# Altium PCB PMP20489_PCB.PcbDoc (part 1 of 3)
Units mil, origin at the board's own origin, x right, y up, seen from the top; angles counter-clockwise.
Board outline 4000 x 6000 mil, 8 copper layers (Top Layer, Signal Layer 1, Signal Layer 2, Signal Layer 3, Signal Layer 4, Signal Layer 5, Signal Layer 6, Bottom Layer), stack 63 mil thick; 331 components, 128 nets, 876 pads, 1027 vias.
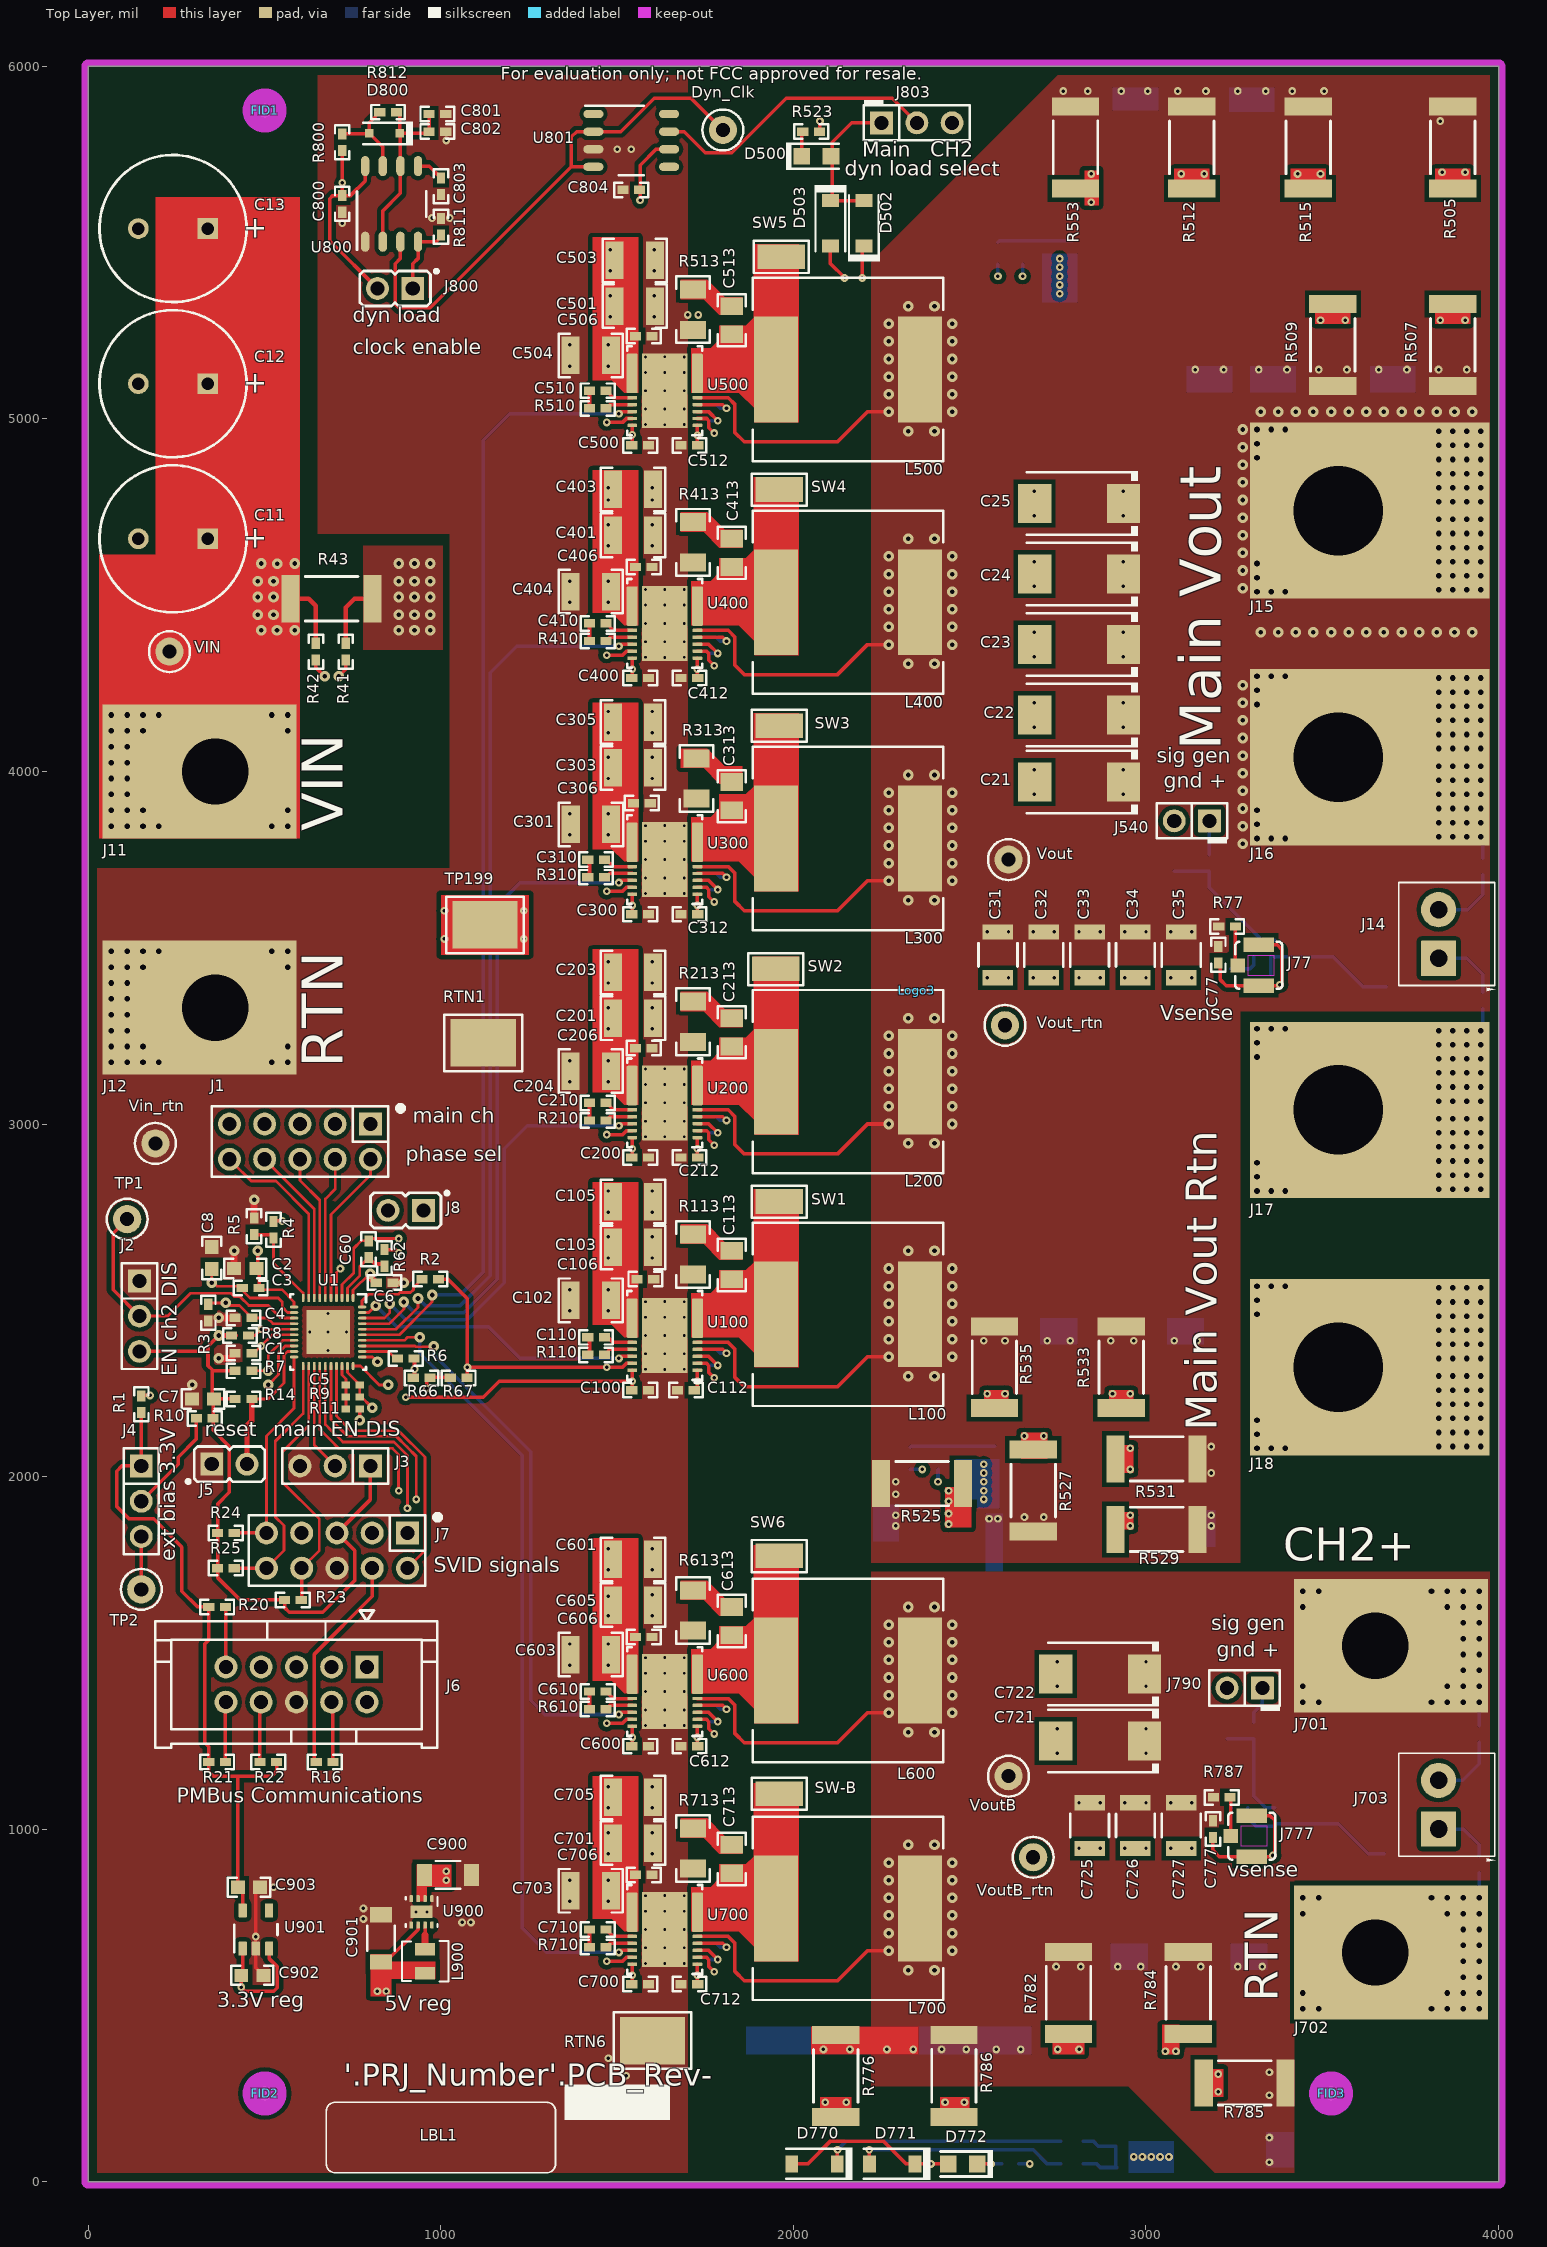
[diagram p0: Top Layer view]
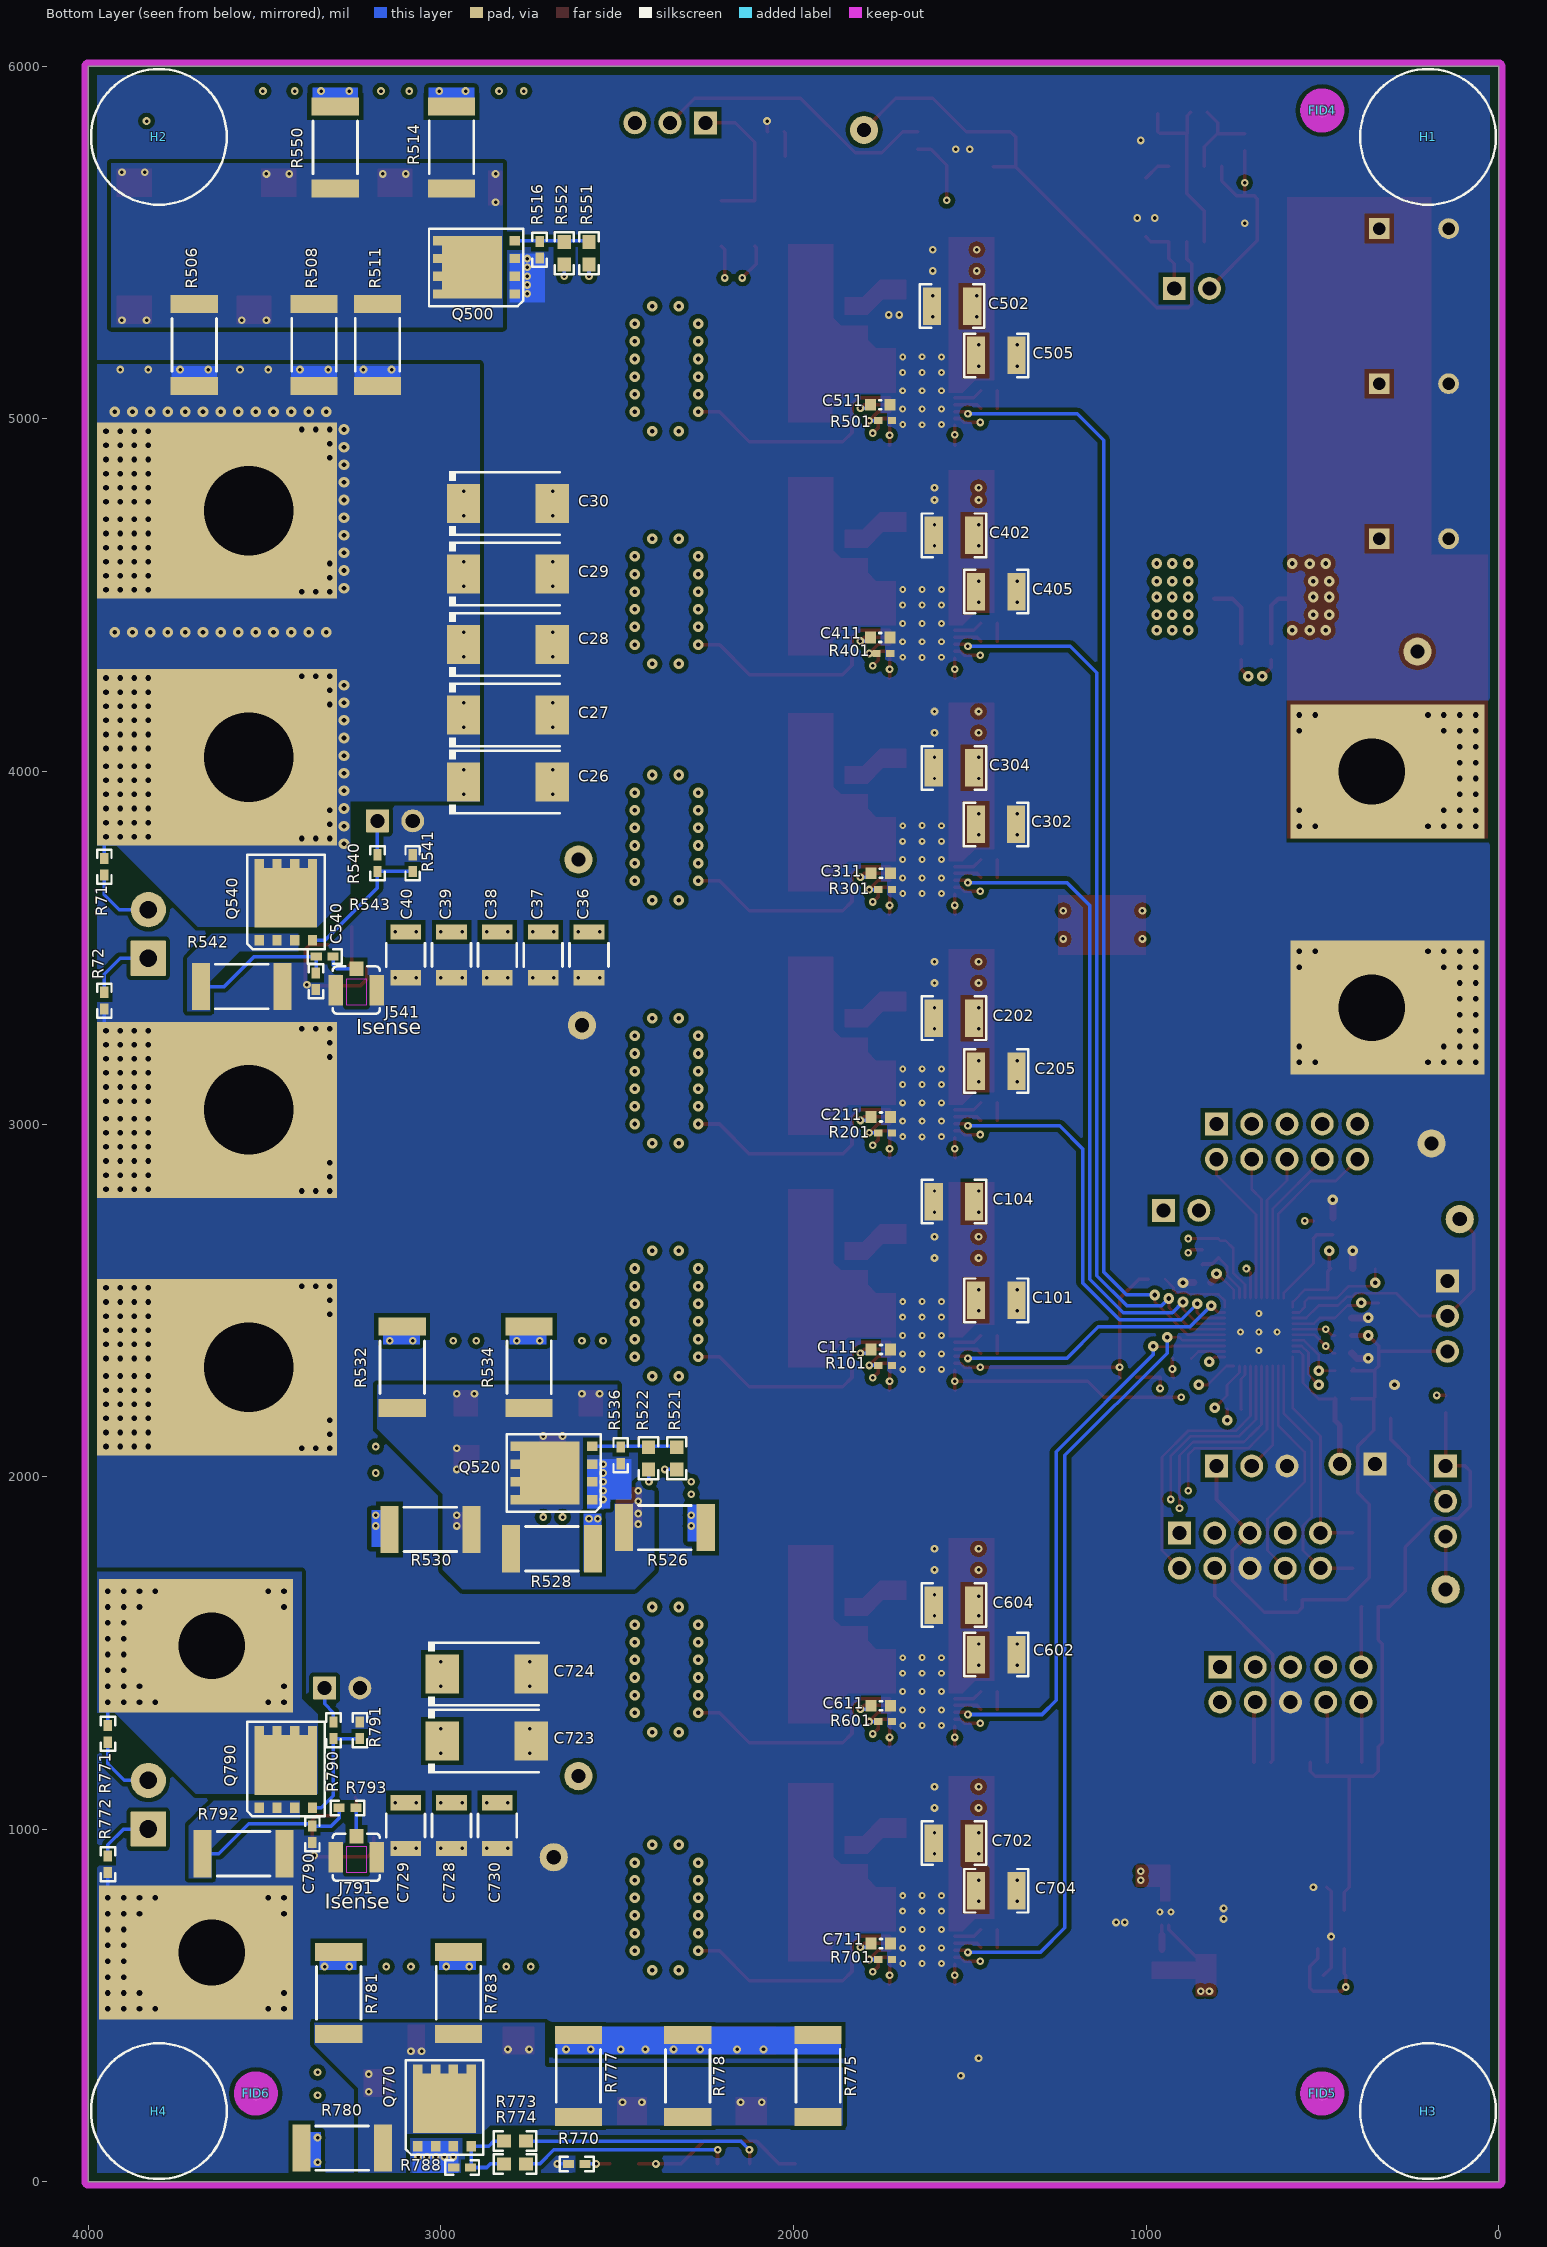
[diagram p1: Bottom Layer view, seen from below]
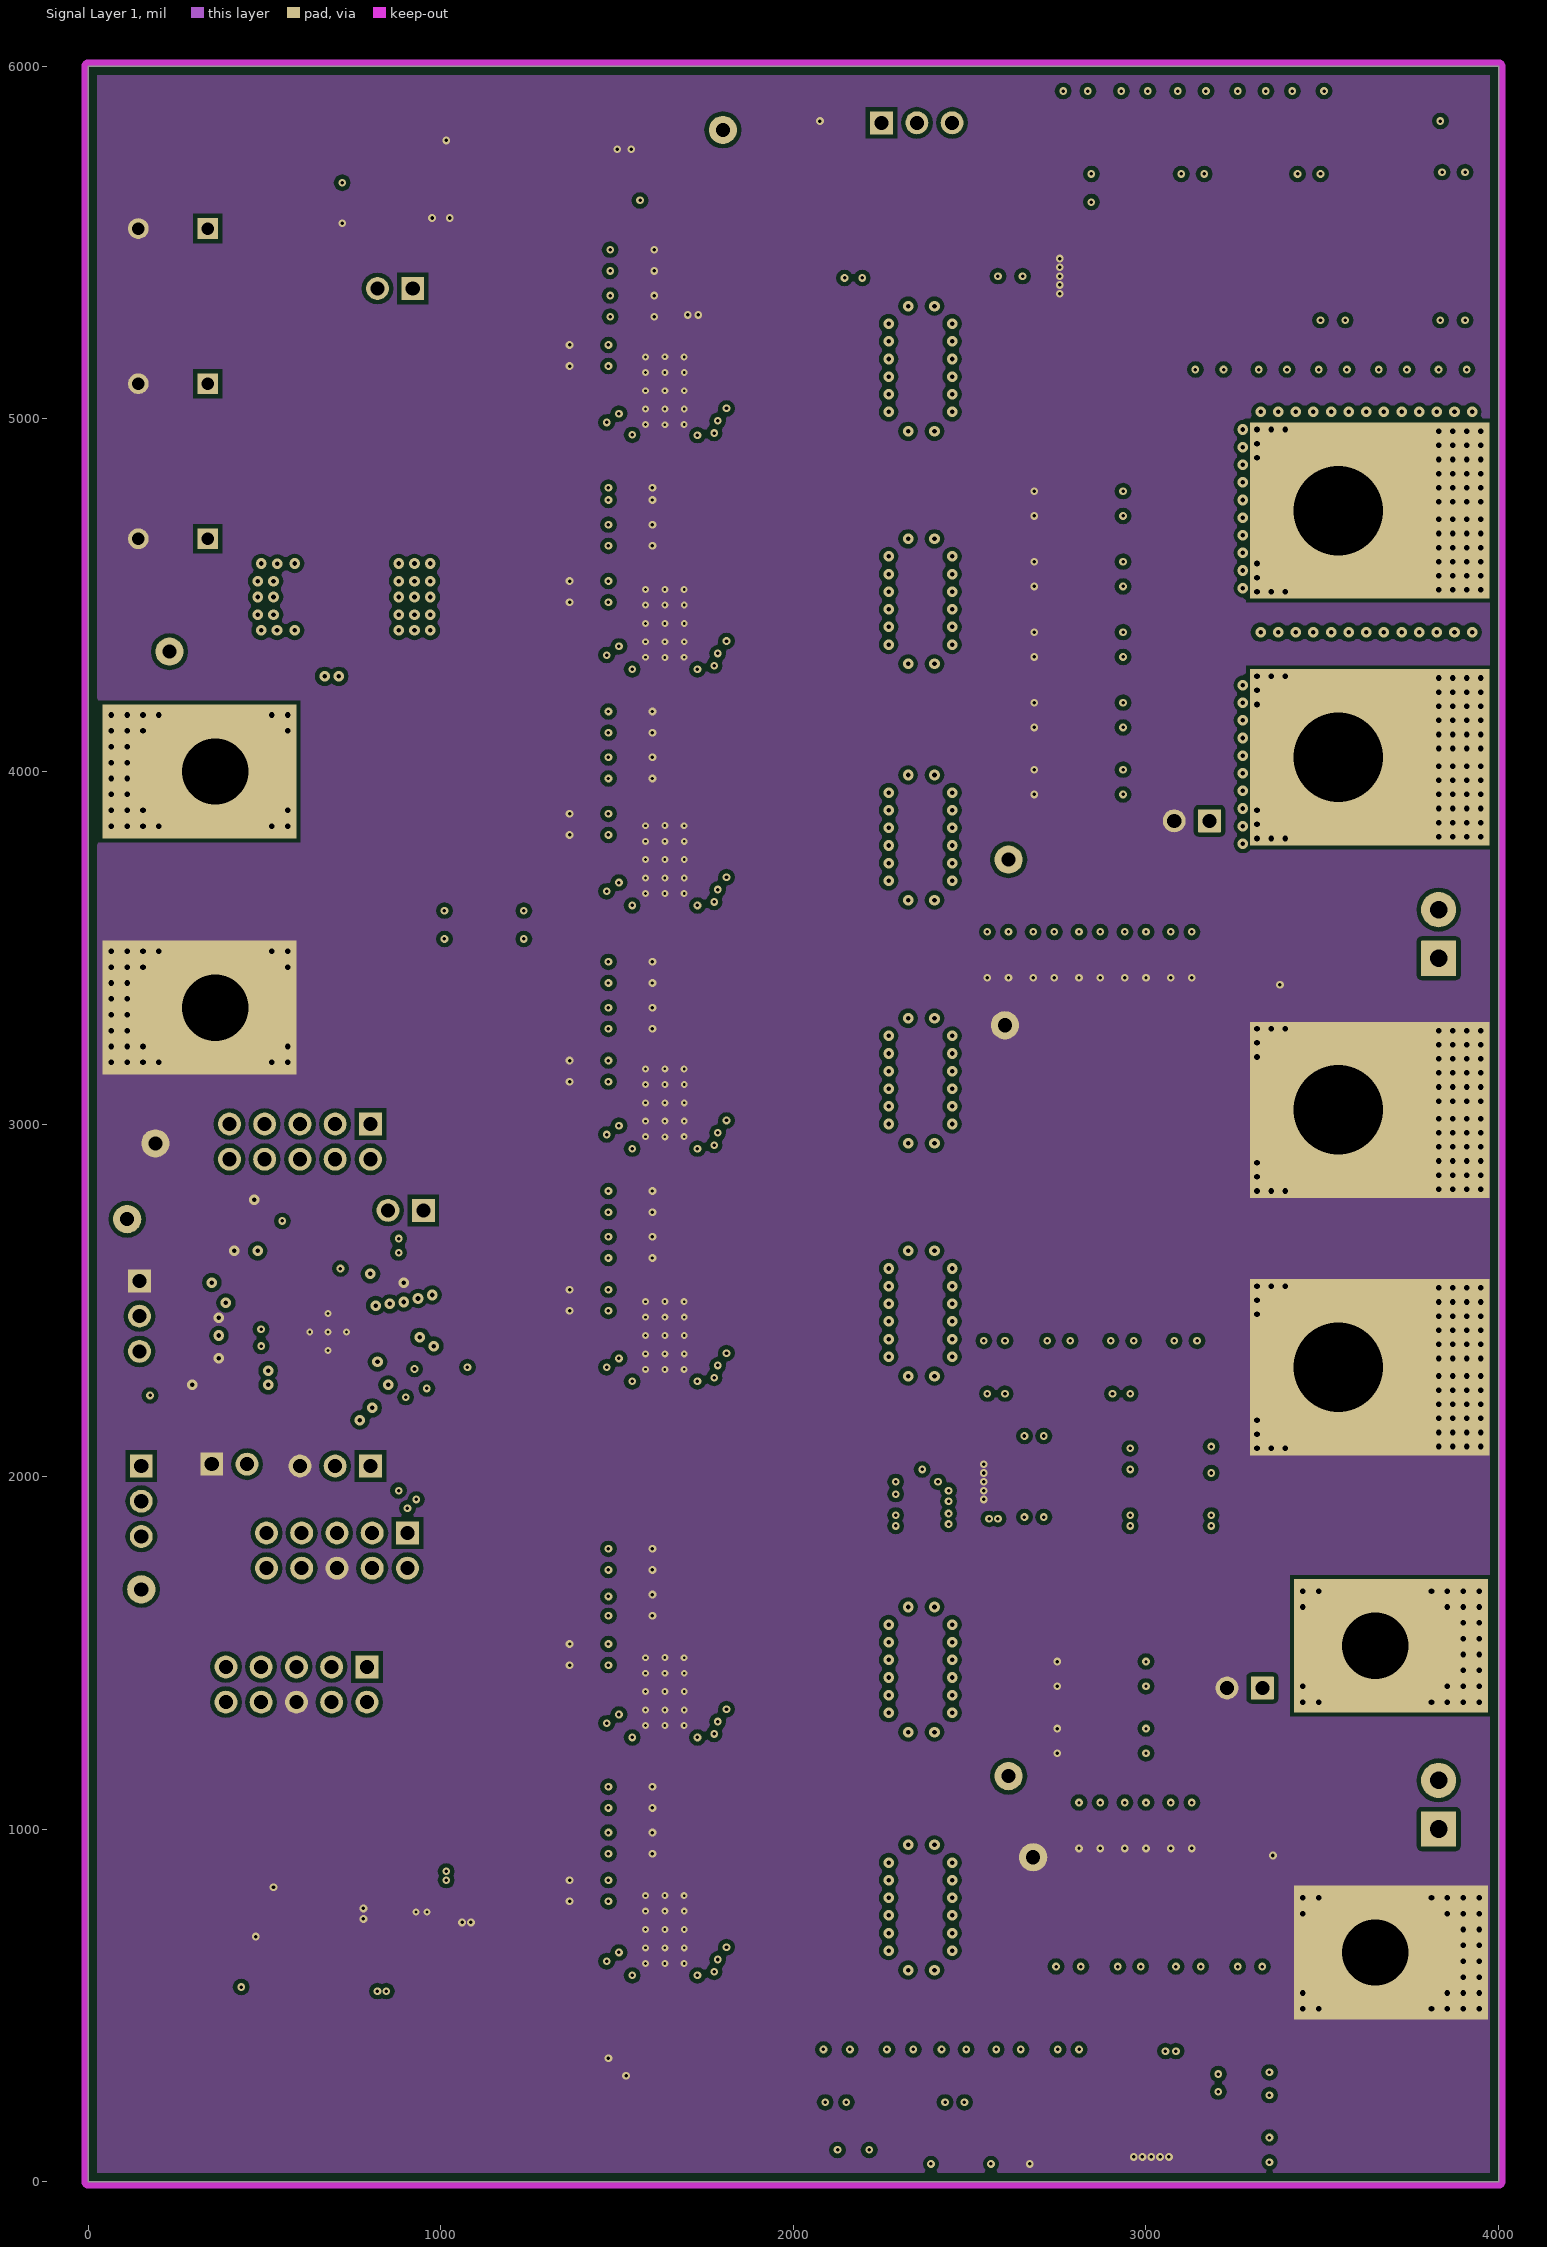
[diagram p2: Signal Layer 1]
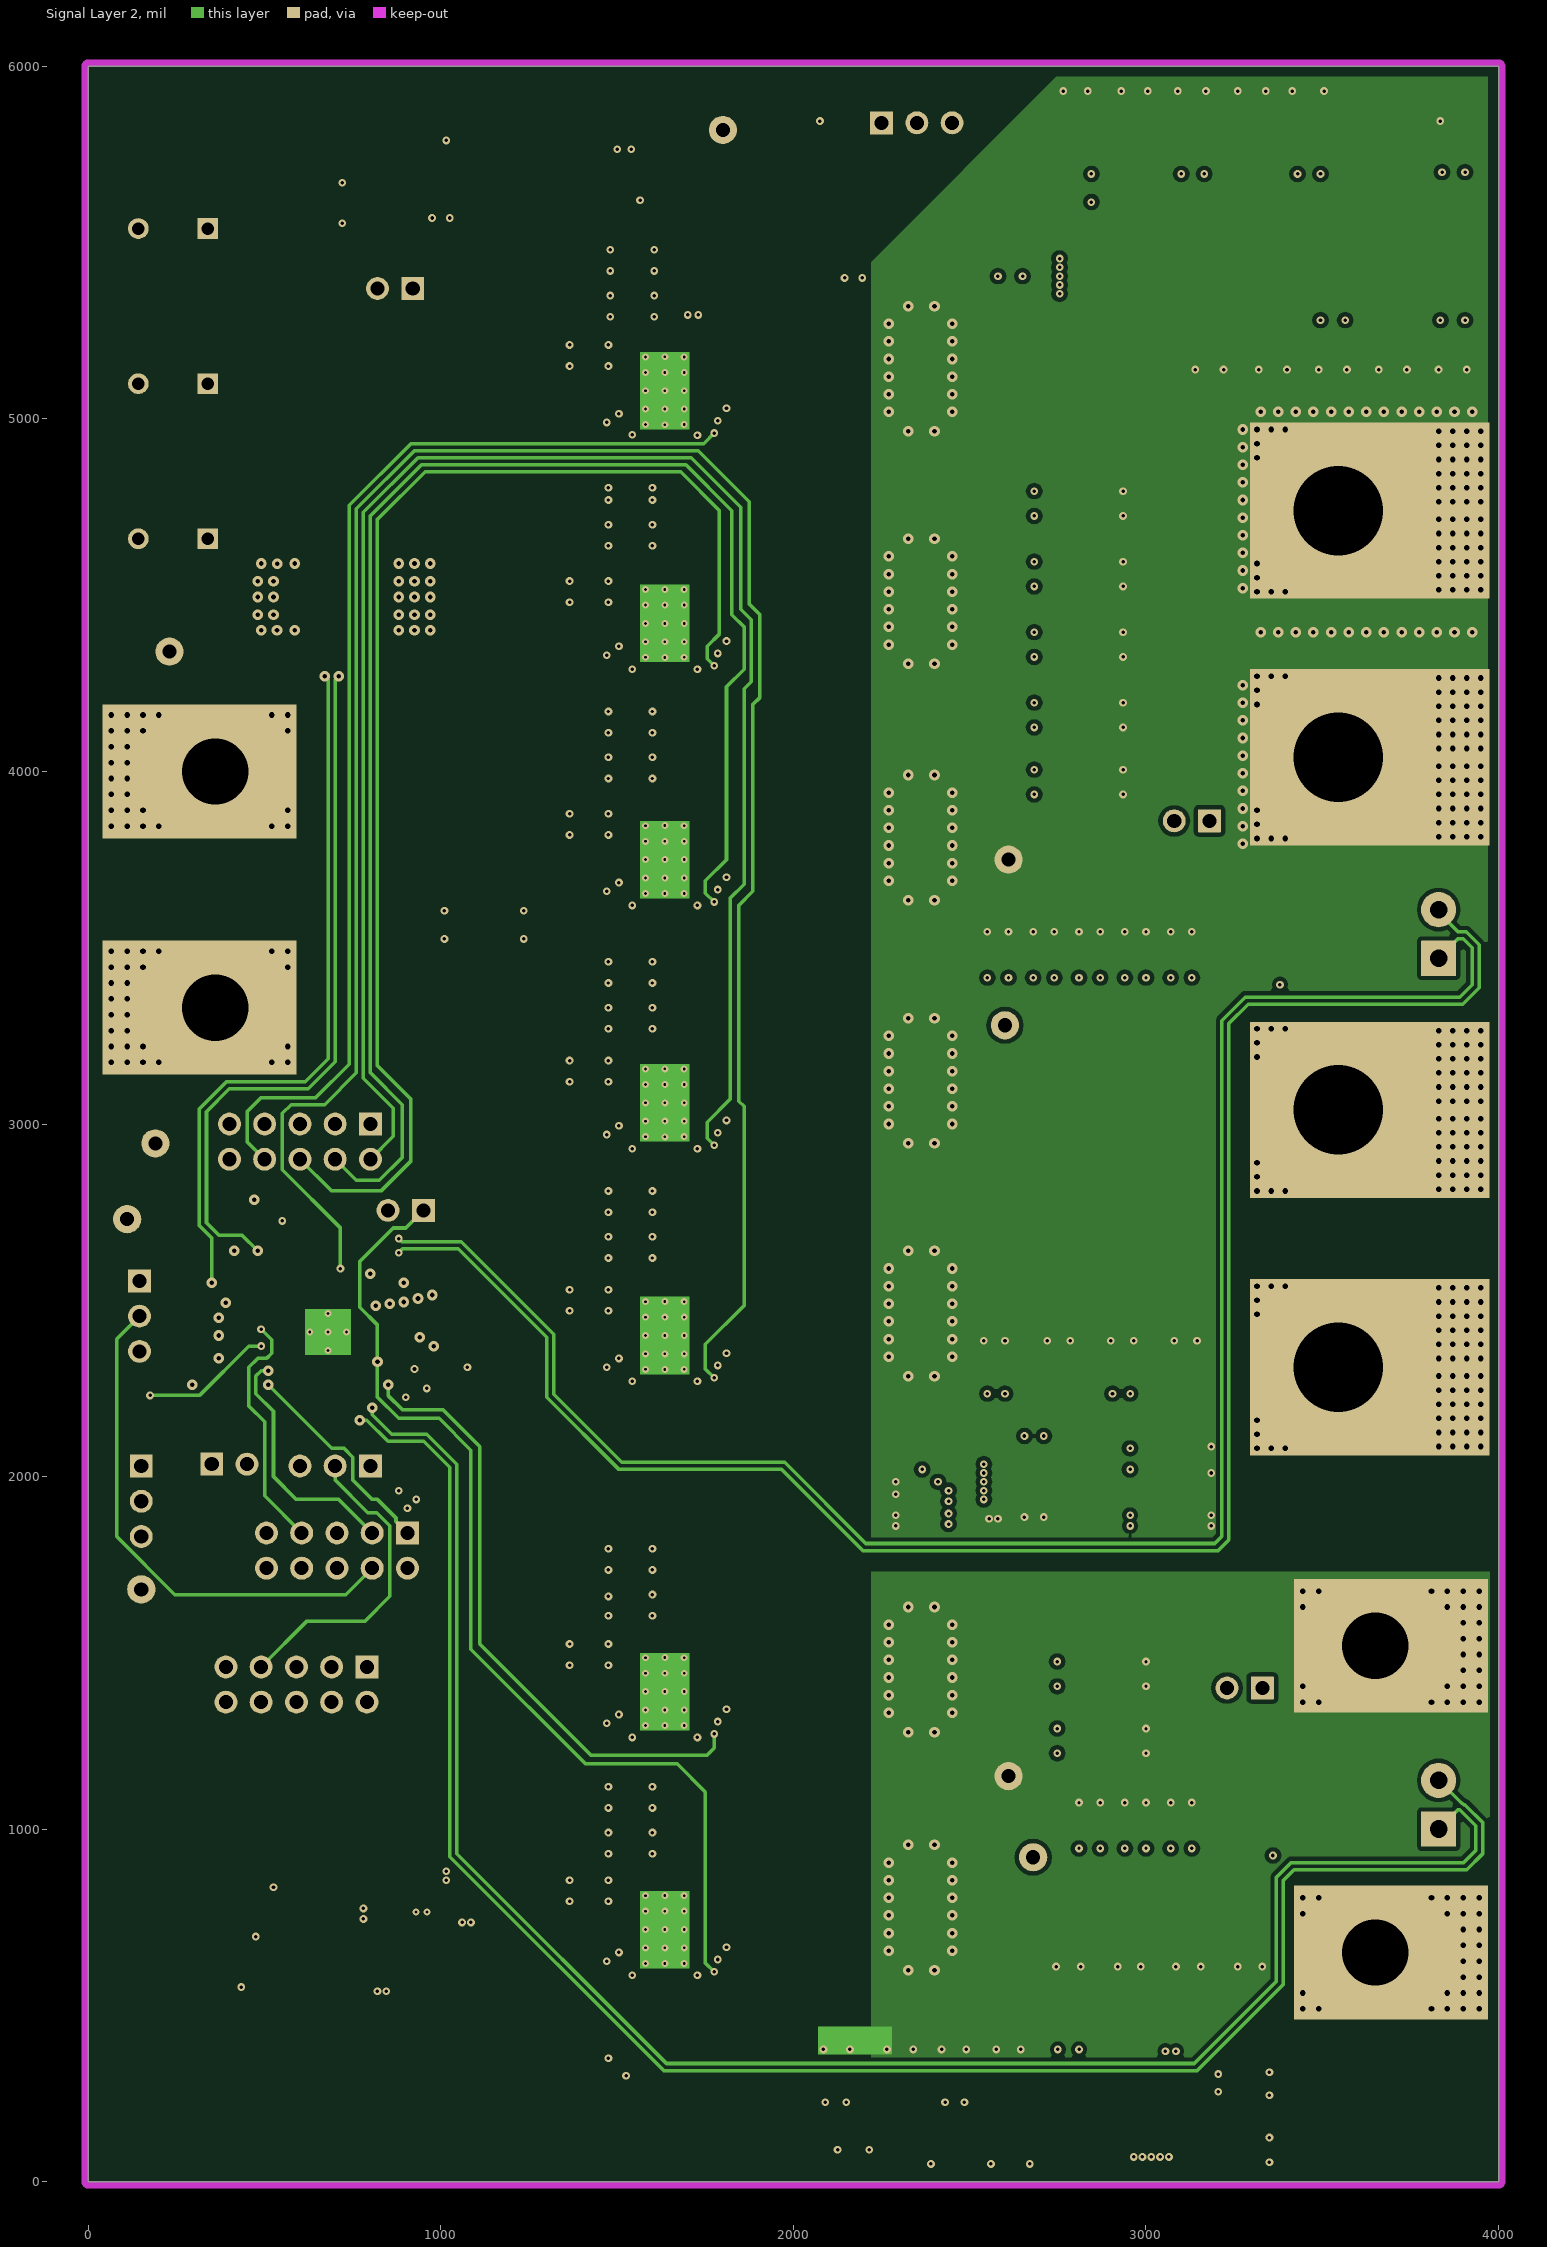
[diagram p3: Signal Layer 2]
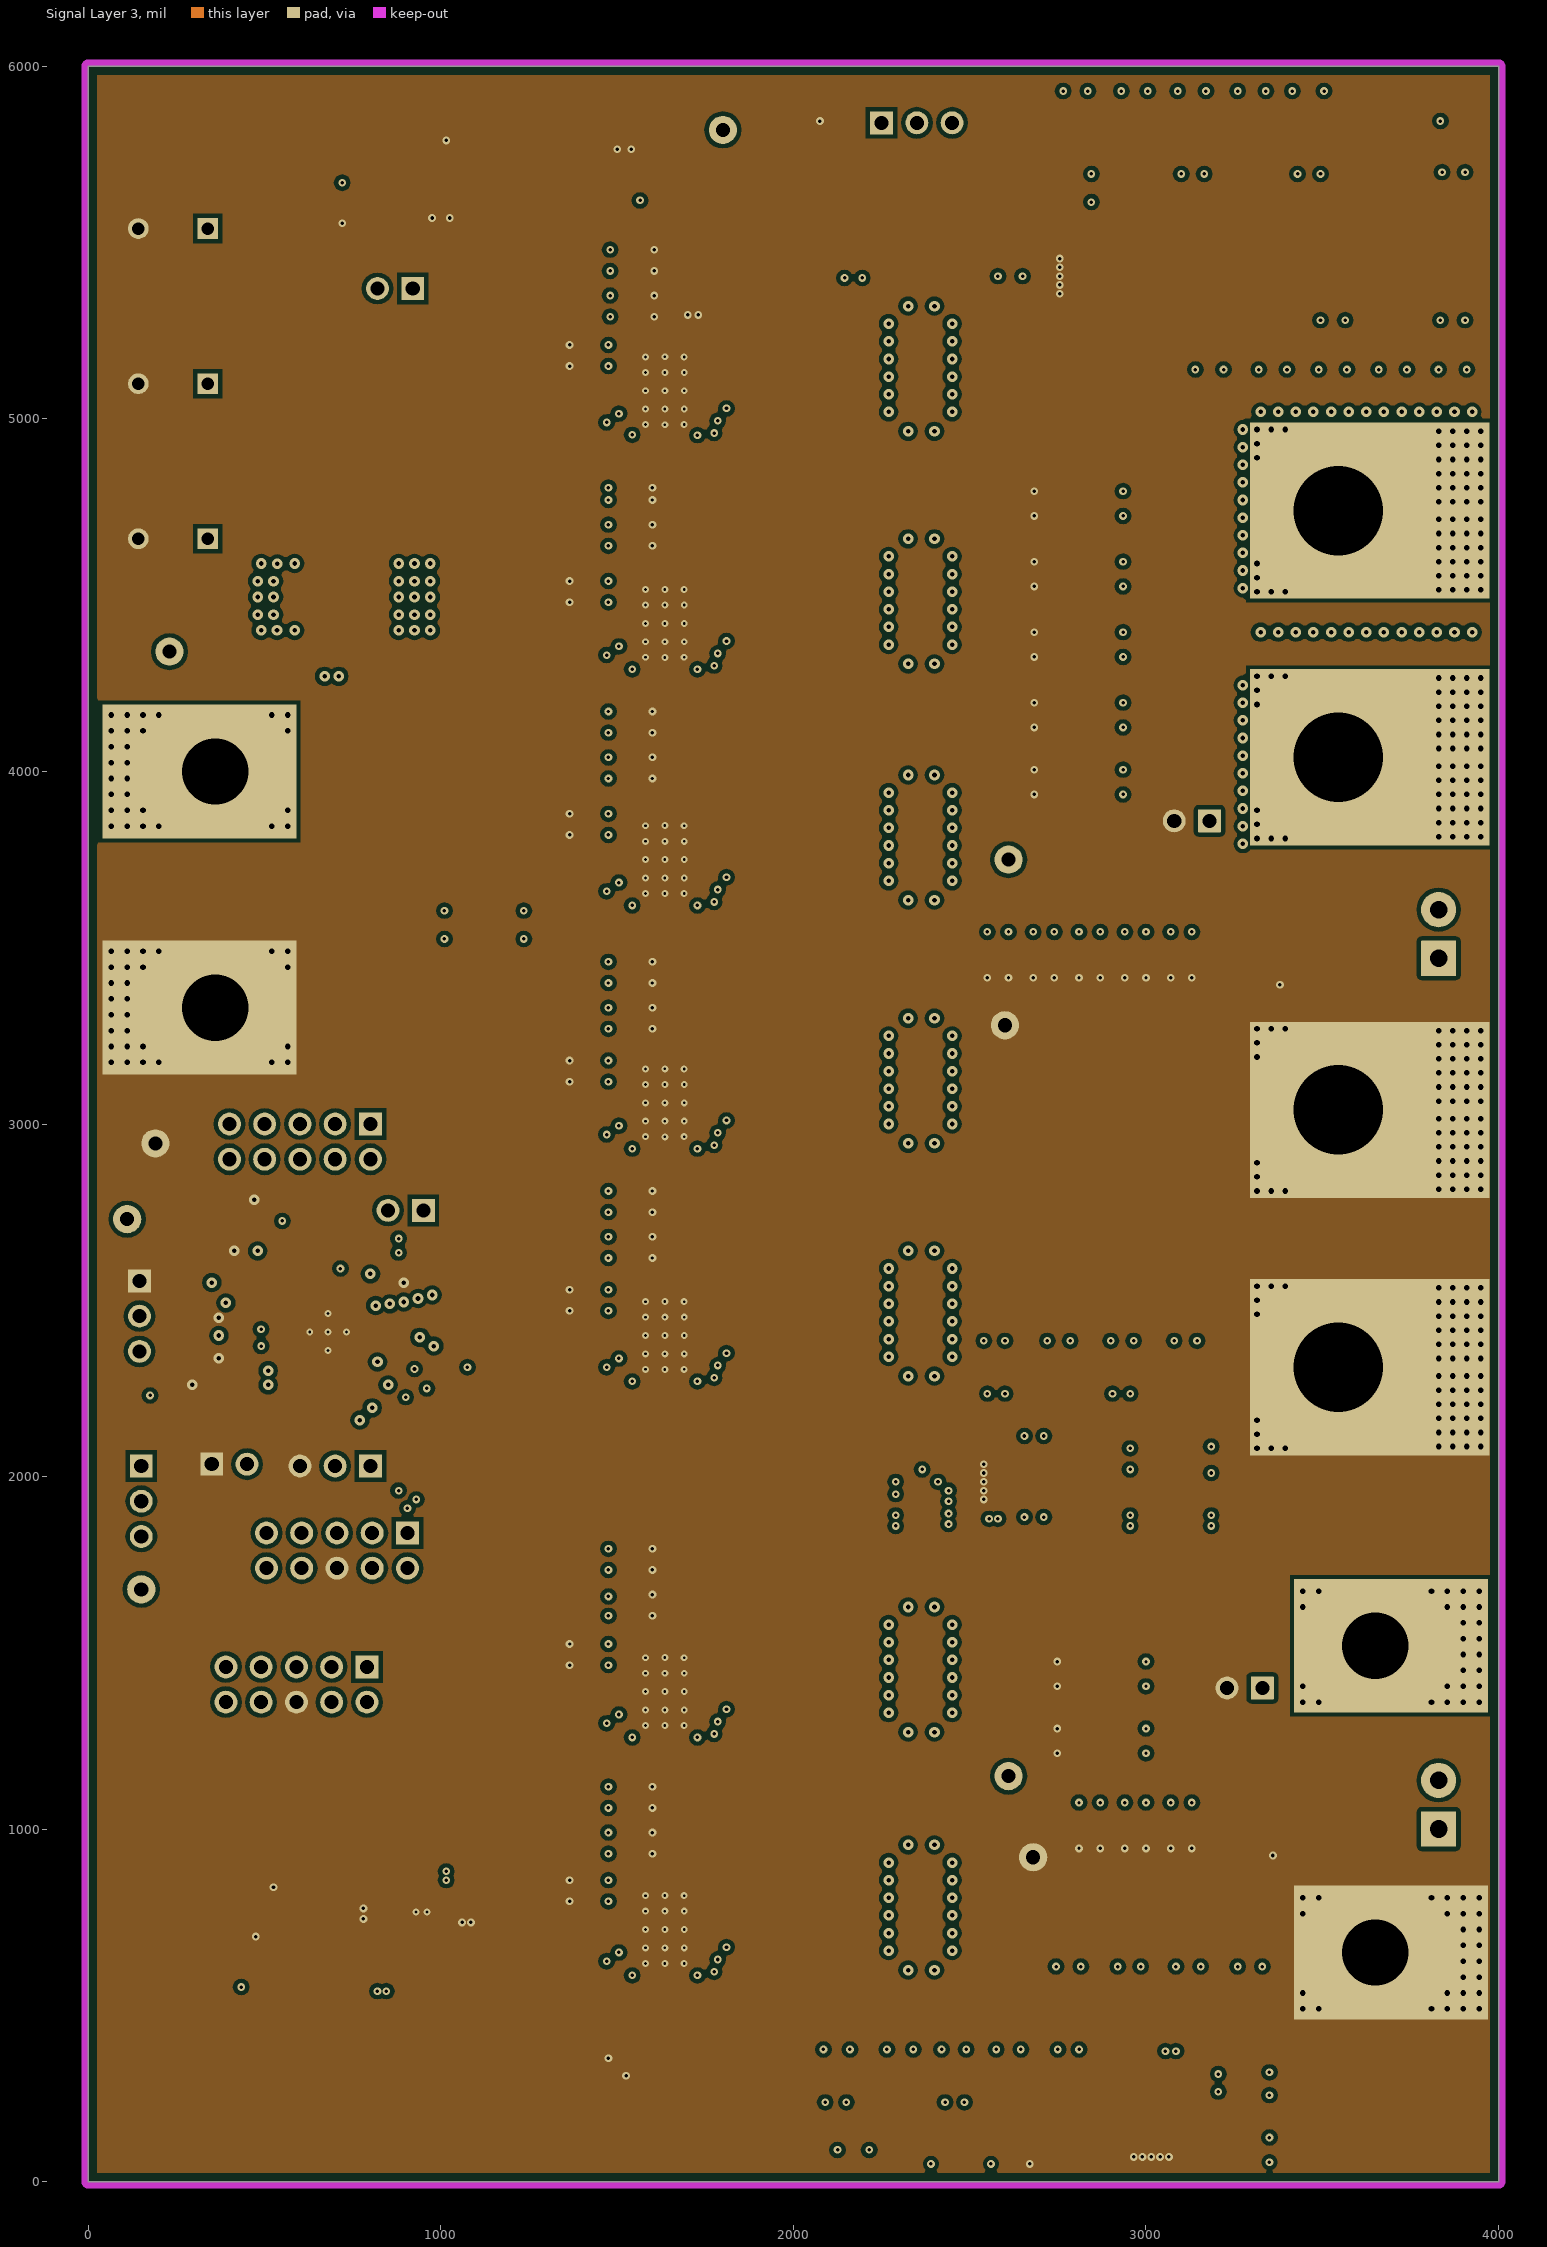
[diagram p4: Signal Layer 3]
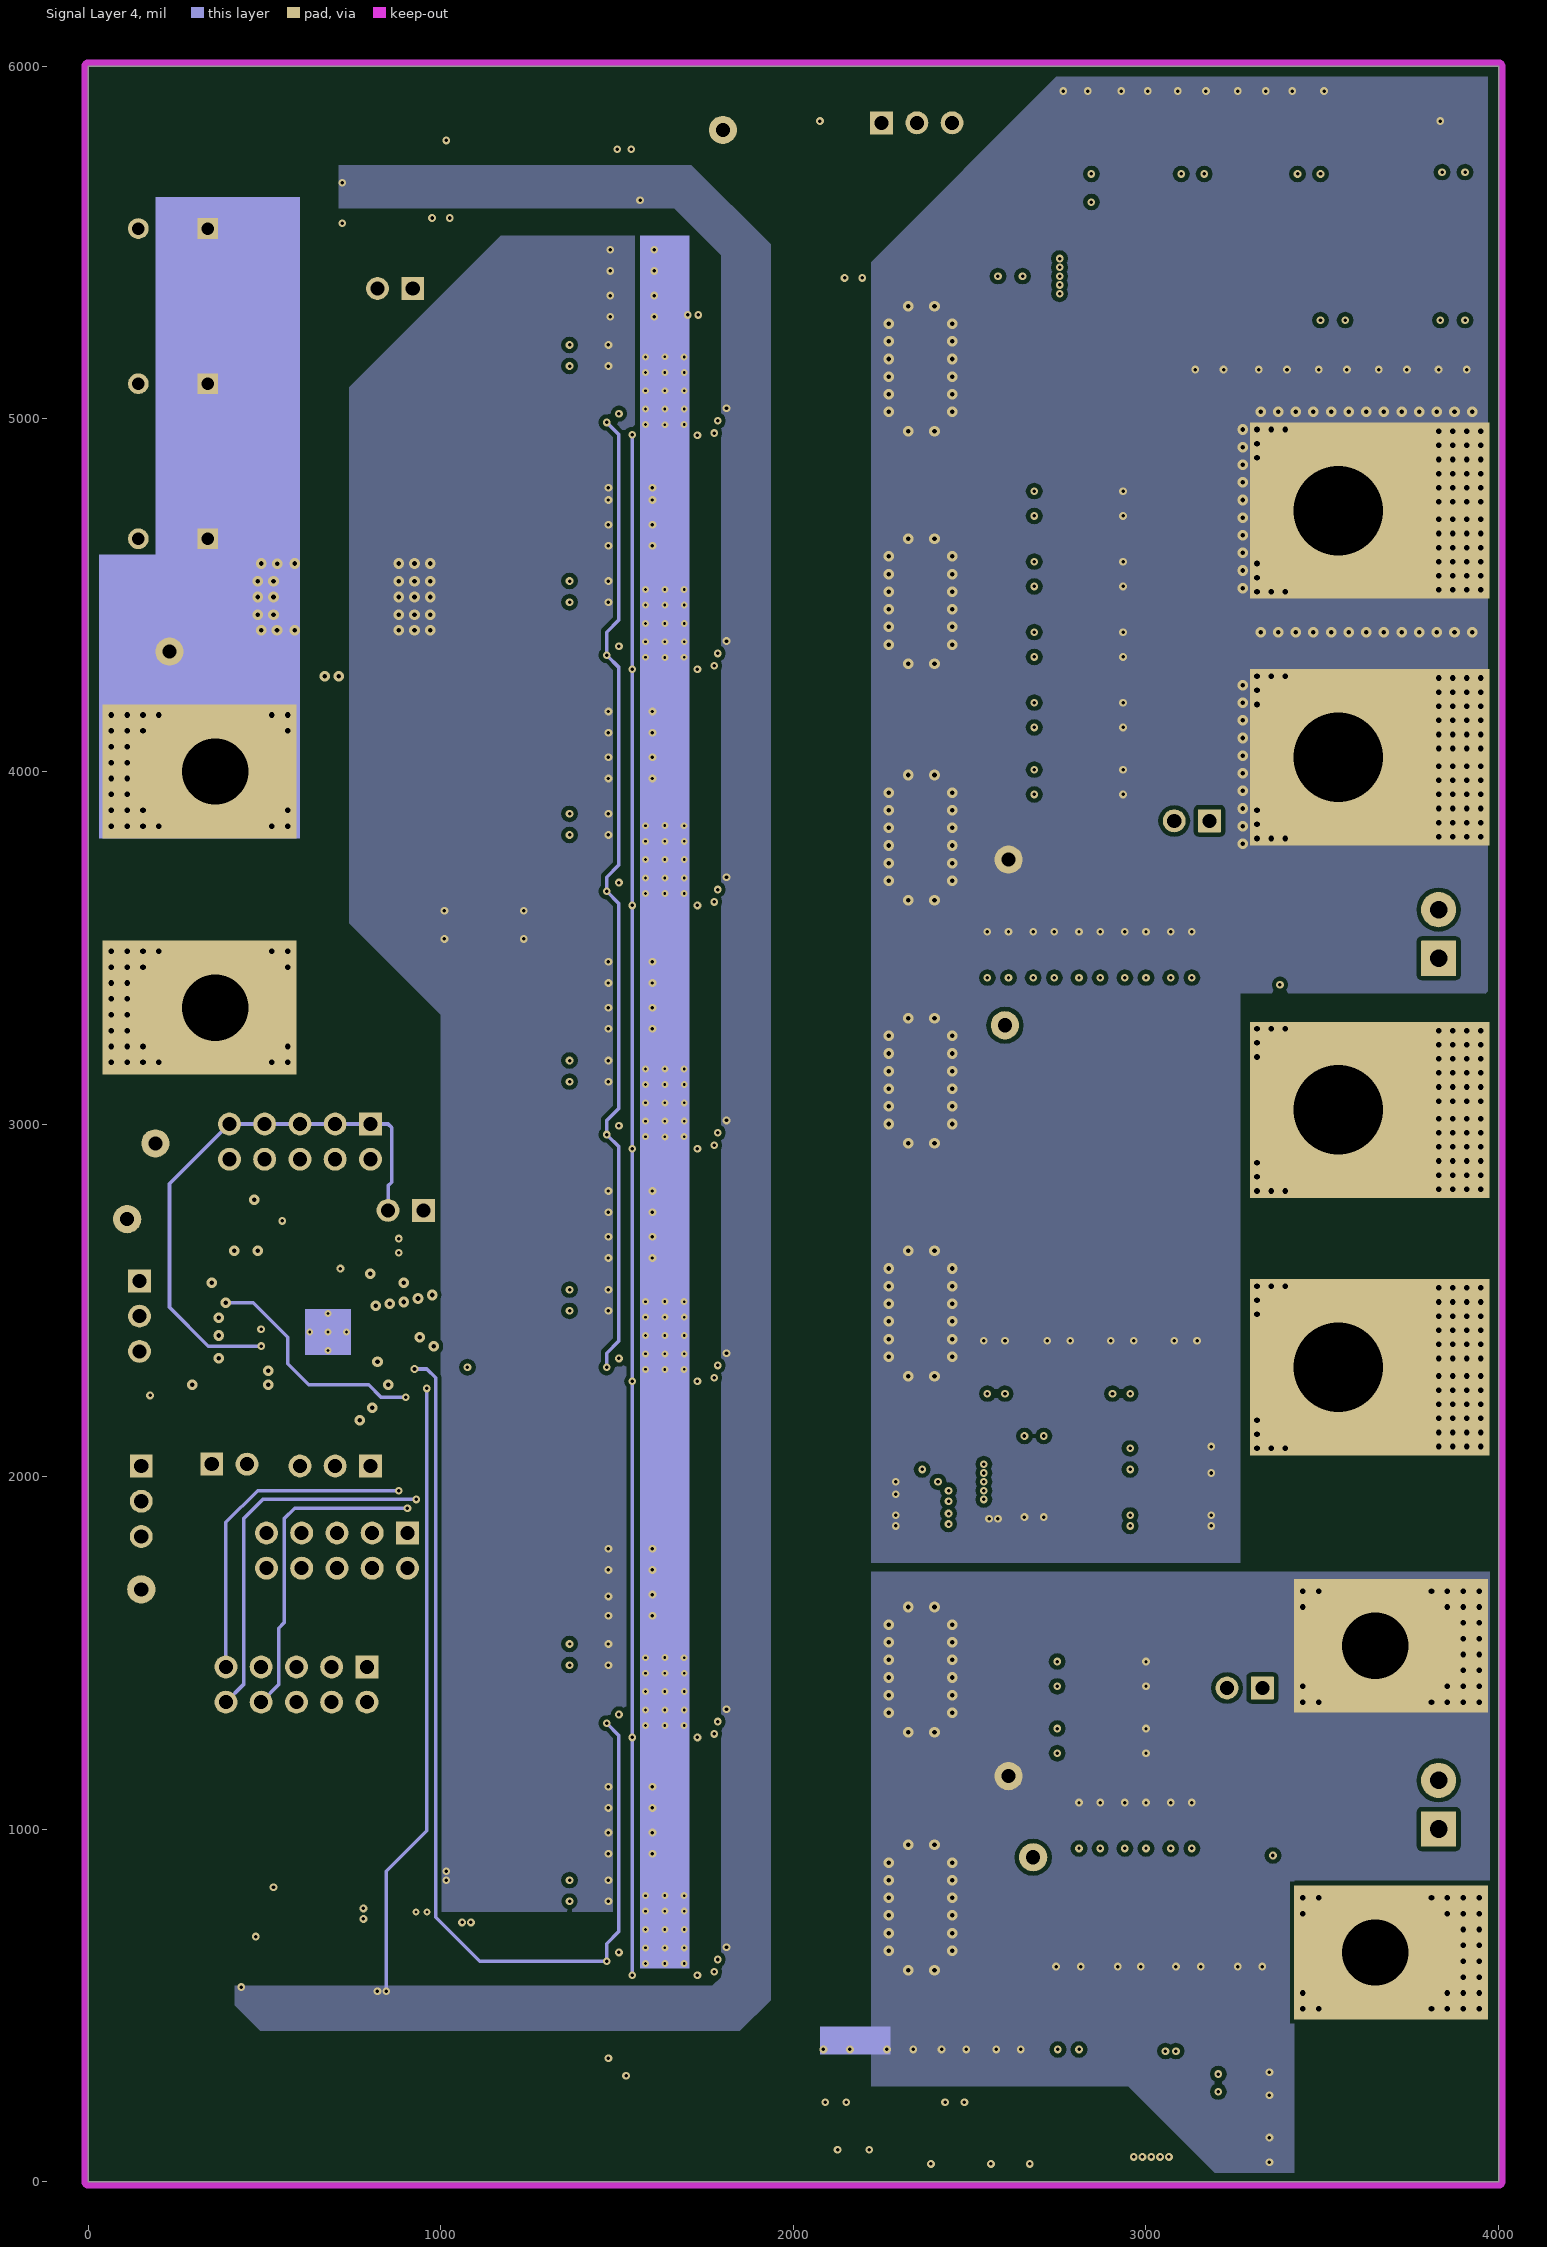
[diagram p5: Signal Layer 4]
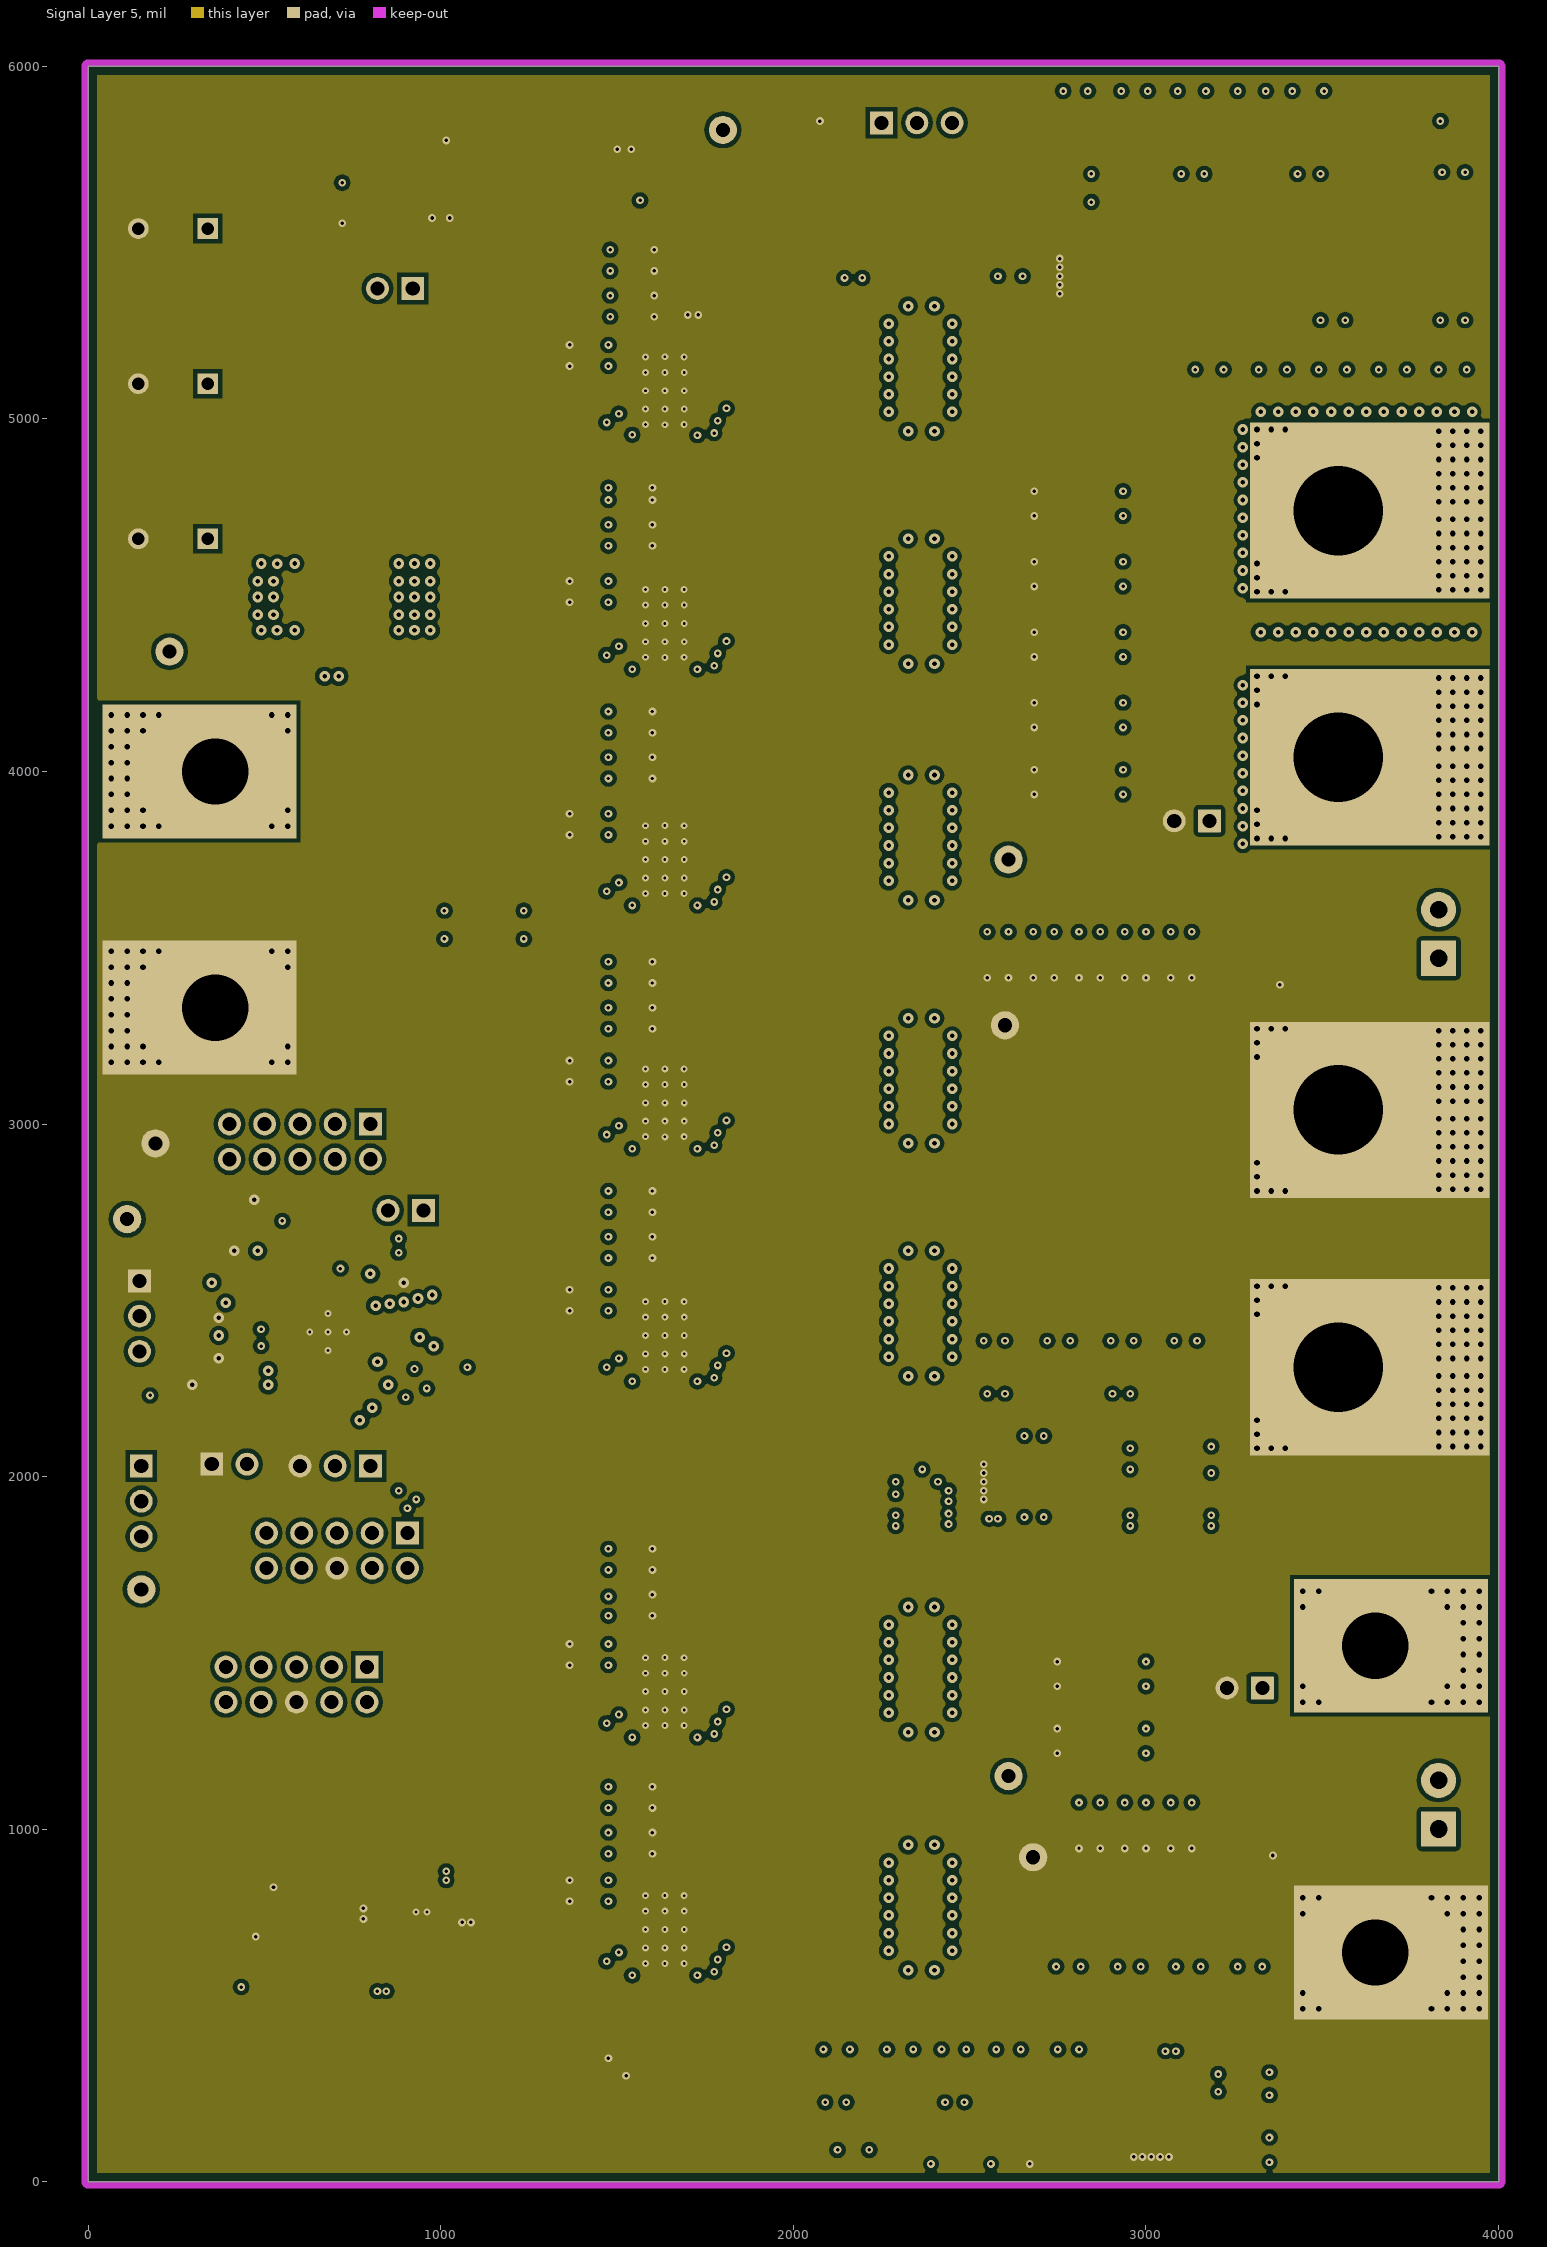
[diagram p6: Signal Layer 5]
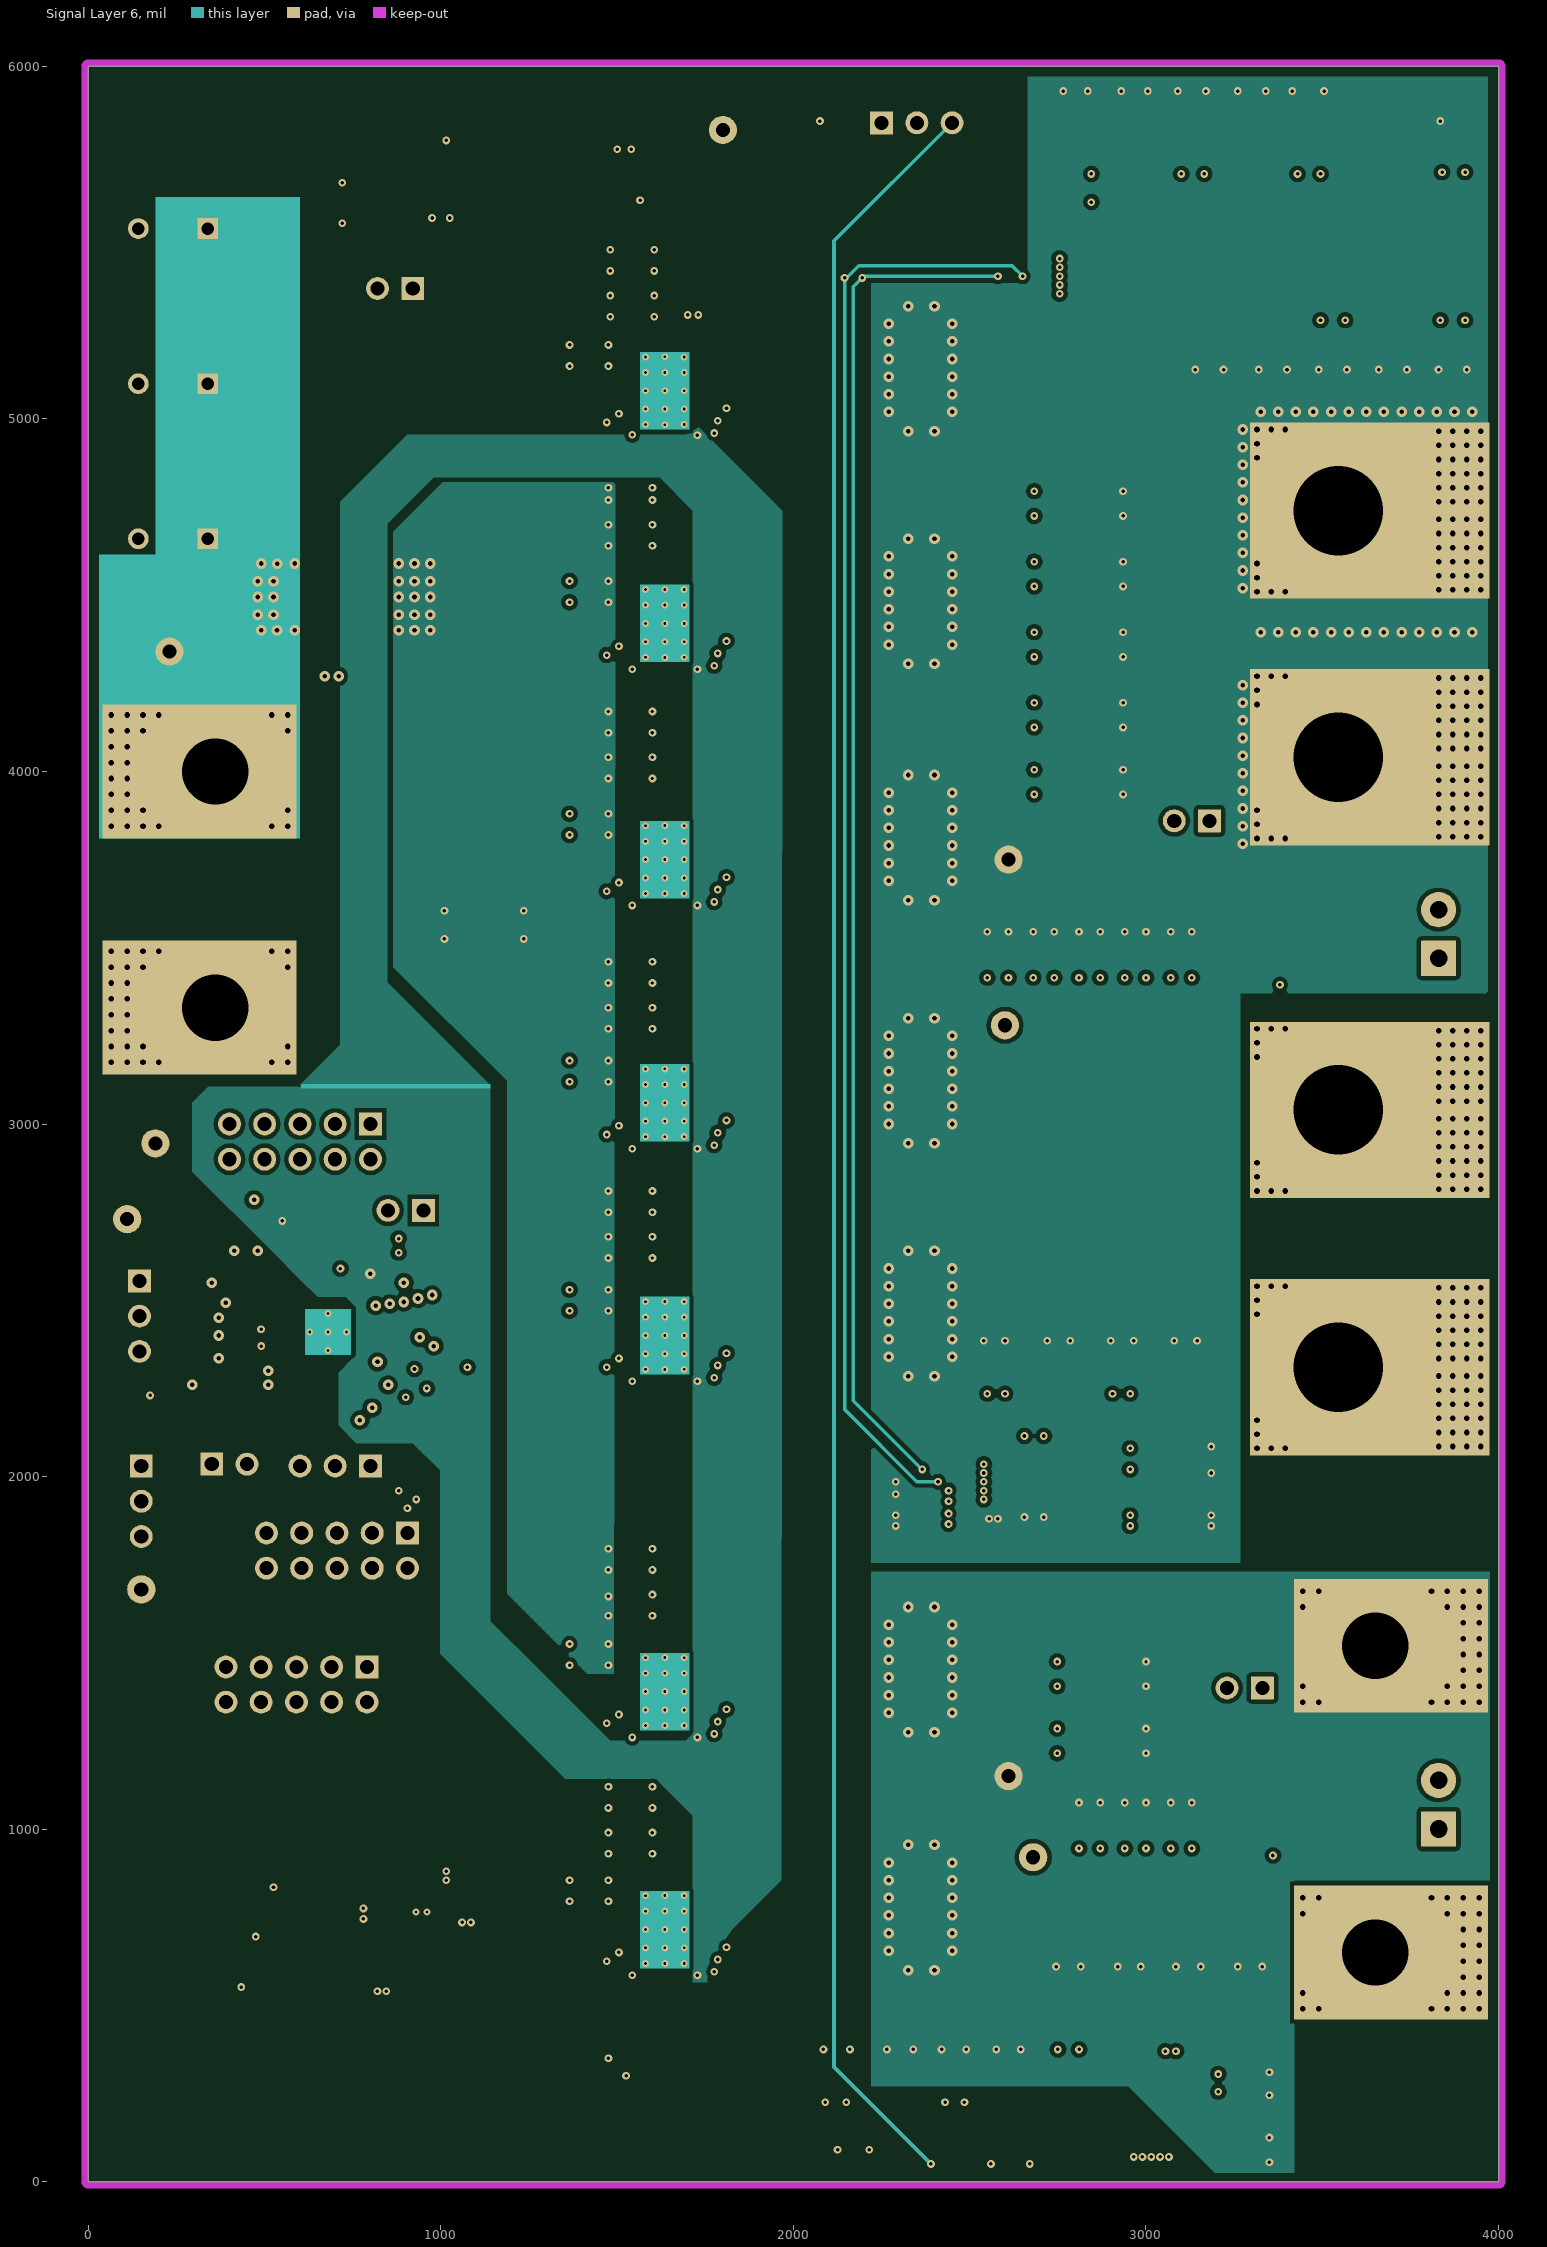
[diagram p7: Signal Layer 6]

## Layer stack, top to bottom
Top Solder: solder mask 0.4, Solder Resist, Dk 3.5
Top Layer: signal copper 2.1
Dielectric1: core 6, FR-4 High TG, Dk 4.8
Signal Layer 1: signal copper 2.8
Dielectric 3: prepreg 6, FR-4 High TG, Dk 4.8
Signal Layer 2: signal copper 2.8
Dielectric 4: core 6, FR-4 High TG, Dk 4.8
Signal Layer 3: signal copper 2.8
Dielectric 5: prepreg 6, FR-4 High TG, Dk 4.8
Signal Layer 4: signal copper 2.8
Dielectric 6: core 6, FR-4 High TG, Dk 4.8
Signal Layer 5: signal copper 2.8
Dielectric 7: prepreg 6, FR-4 High TG, Dk 4.8
Signal Layer 6: signal copper 2.8
Dielectric 2: core 6, FR-4 High TG, Dk 4.8
Bottom Layer: signal copper 2.1
Bottom Solder: solder mask 0.4, Solder Resist, Dk 3.5

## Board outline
0,0 4000,0 4000,6000 0,6000

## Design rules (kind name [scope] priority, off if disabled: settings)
AcuteAngle [All] p1: minimum=4.50000000000000E+0001 checktracksonly=FALSE
AssemblyTestPointUsage [All] p1: valid=2
BoardOutlineClearance BoardOutlineClearance_MountingHoles [OnCopper and InComponentClass('Mounting Holes')] p1: gap=40
BoardOutlineClearance BoardOutlineClearance_Poly [OnCopper and IsPoly] p2: gap=25
BoardOutlineClearance [OnCopper and Not InComponentClass('Logo') and not InComponentClass('FiducialMark') and not InRegion(1000,500,4000,800) and not InPoly] p3: gap=25
Clearance Clearance_Keepouts [((IsTrack Or IsArc) And Not InPoly) And IsFree and IsKeepOut vs ((IsTrack Or IsArc) And Not InPoly) And IsFree and IsKeepOut] p1: gap=0
Clearance Clearance_Poly [InPolygon] p2: gap=12
Clearance [All] p3: gap=7.8
ComponentClearance ComponentClearance_MountingHoles_FiducialMarks [InComponentClass('Mounting Holes') vs InComponentClass('FiducialMark')] p1: gap=50 collisioncheckmode=3 verticalgap=10 showdistances=FALSE
ComponentClearance ComponentClearance_Shunt [InComponentClass('Header') vs InComponentClass('Shunt')] p2: gap=0 collisioncheckmode=3 verticalgap=0 showdistances=FALSE
ComponentClearance ComponentClearance_Logo [InComponentClass('Logo')] p3: gap=50 collisioncheckmode=3 verticalgap=10 showdistances=FALSE
ComponentClearance ComponentClearance_ScrewToNut [(HasFootprint('NY PMS 440 0025 PH')) vs (HasFootprint('Keystone_1902C'))] p4: gap=5 collisioncheckmode=3 verticalgap=10 showdistances=FALSE
ComponentClearance ComponentClearance_MountingHoles [InComponentClass('Mounting Holes')] p5: gap=150 collisioncheckmode=3 verticalgap=150 showdistances=FALSE
ComponentClearance ComponentClearance_SmallPassives [HasFootprint('0201*') or HasFootprint('0402*') or HasFootprint('0508') or HasFootprint('0603*') or HasFootprint('0612') or HasFootprint('0805*') or HasFootprint('0815*') or HasFootprint('0830*') or HasFootprint('1206*') or HasFootprint('1210*') or HasFootprint('1808*') or HasFootprint('1812*') or HasFootprint('1825*') or HasFootprint('2010*') or HasFootprint('2220*') or HasFootprint('2225*') or HasFootprint('2512*') or HasFootprint('2728*') or HasFootprint('3518*') vs HasFootprint('0201*') or HasFootprint('0402*') or HasFootprint('0508') or HasFootprint('0603*') or HasFootprint('0612') or HasFootprint('0805*') or HasFootprint('0815*') or HasFootprint('0830*') or HasFootprint('1206*') or HasFootprint('1210*') or HasFootprint('1808*') or HasFootprint('1812*') or HasFootprint('1825*') or HasFootprint('2010*') or HasFootprint('2220*') or HasFootprint('2225*') or HasFootprint('2512*') or HasFootprint('2728*') or HasFootprint('3518*')] p6: gap=10 collisioncheckmode=3 verticalgap=10 showdistances=FALSE
ComponentClearance ComponentClearance_THtoSMT [IsThruComponent vs IsSMTComponent] p7: gap=20 collisioncheckmode=3 verticalgap=20 showdistances=FALSE
ComponentClearance ComponentClearance_THtoTH [IsThruComponent vs IsThruComponent] p8: gap=20 collisioncheckmode=3 verticalgap=20 showdistances=FALSE
ComponentClearance [All] p9: gap=10 collisioncheckmode=3 verticalgap=10 showdistances=FALSE
DiffPairsRouting [All] p1: maxlimit=100 minlimit=10 mostfreqgap=10 toplayer_minwidth=15 toplayer_maxwidth=15 toplayer_prefwidth=15 midlayer1_minwidth=15 midlayer1_maxwidth=15 midlayer1_prefwidth=15 midlayer2_minwidth=15 midlayer2_maxwidth=15 midlayer2_prefwidth=15 midlayer3_minwidth=15 midlayer3_maxwidth=15 midlayer3_prefwidth=15 midlayer4_minwidth=15 midlayer4_maxwidth=15 midlayer4_prefwidth=15 midlayer5_minwidth=15 midlayer5_maxwidth=15 midlayer5_prefwidth=15 midlayer6_minwidth=15 midlayer6_maxwidth=15 midlayer6_prefwidth=15 bottomlayer_minwidth=15 bottomlayer_maxwidth=15 bottomlayer_prefwidth=15 maxuncoupledlength=1000
FabricationTestPointUsage TestPointUsage [All] p1: valid=2 allowmultiple=FALSE
FabricationTestpoint Testpoint [All] p1: side=3 testpointundercomponent=TRUE minsize=40 maxsize=100 preferedsize=60 minholesize=0 maxholesize=40 preferedholesize=32 testpointgrid=1 allowsidetop=TRUE allowsidebottom=TRUE usegrid=TRUE gridtolerance=0.01
FanoutControl Fanout_LCC [IsLCC] p1: bgadir=Out bgaviamode=Centered fanoutstyle=Auto fanoutdirection=Alternating viagrid=1 // Fanout_LCC (Default Rule)
FanoutControl Fanout_BGA [IsBGA] p2: bgadir=Out bgaviamode=Centered fanoutstyle=Auto fanoutdirection=Alternating viagrid=1 // Fanout_BGA (Default Rule)
FanoutControl Fanout_Default [All] p4: bgadir=Out bgaviamode=Centered fanoutstyle=Auto fanoutdirection=Alternating viagrid=1 // Fanout_Default (Default Rule)
FanoutControl Fanout_Small [(CompPinCount < 5)] p5: bgadir=Out bgaviamode=Centered fanoutstyle=Auto fanoutdirection=OutThenIn viagrid=1 // Fanout_Small (Default Rule)
HoleSize [All] p1: absolutevalues=TRUE maxlimit=255 minlimit=7.87 maxpercent=80.000 minpercent=20.000
MinimumAnnularRing MinimumAnnularRing_ThermalPadVias [IsVia and InAnyComponent] p1: minimumring=5.91
MinimumAnnularRing [All] p2: minimumring=5.9
MinimumSolderMaskSliver MinimumSolderMaskSliver_Logo [InComponentClass('Logo') vs InComponentClass('Logo')] p1: minsoldermaskwidth=0.7
MinimumSolderMaskSliver [All] p2: minsoldermaskwidth=3.94
PlaneConnect [All] p1: planeconnectstyle=Relief reliefexpansion=10 reliefentries=4 reliefconductorwidth=10 reliefairgap=10
PolygonConnect [All] p1: connectstyle=Direct reliefconductorwidth=10 reliefentries=4 polygonreliefangle="90 Angle" airgapwidth=10
RoutingVias ThermalPadVias [IsVia and InAnyComponent] p1: holewidth=7.87 width=19.68 viastyle="Through Hole" minholewidth=7.87 minwidth=19.68 maxholewidth=16 maxwidth=32
RoutingVias [All] p2: holewidth=16 width=34 viastyle="Through Hole" minholewidth=7.87 minwidth=19 maxholewidth=40 maxwidth=65
SilkToBoardRegionClearance [Not ((IsComment or IsDesignator) And (Hide <> 'False')) and not InRegion(1000,500,4000,800)] p1:
SilkToSilkClearance SilkToSilkClearance_Pb-FreeLogo [(HasFootprint('Pb-Free_Overlay_Medium') OR HasFootprint('Pb-Free_Overlay_Small')) vs (HasFootprint('Pb-Free_Overlay_Medium') OR HasFootprint('Pb-Free_Overlay_Small'))] p1: silktosilkclearance=0
SilkToSilkClearance [All] p2: silktosilkclearance=3
SilkToSolderMaskClearance SilkToComponentPadClearance [IsPad and InAnycomponent] p1: minsilkscreentomaskgap=4 clearancetoexposedcopper=TRUE
SilkToSolderMaskClearance "Silk to Solder Mask Opening" [All] p2: minsilkscreentomaskgap=3 clearancetoexposedcopper=FALSE
SolderMaskExpansion [All] p1: expansion=1.97
Width [All] p1: maxlimit=100 minlimit=7.8 preferedwidth=10 midlayer1_minwidth=8 midlayer2_minwidth=8 midlayer3_minwidth=8 midlayer4_minwidth=8 midlayer5_minwidth=8 midlayer6_minwidth=8 minimp=50.000000 maximp=50.000000 favimp=50.000000 checkconnectedcopper=TRUE
15 further rules are at their usual default settings.

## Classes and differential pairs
component class PMP20489_TPS53679controller&Ch2PS: C1 C2 C3 C4 C5 C6 C7 C8 C60 C600 C601 C602 C603 C604 C605 C606 C610 C611 C612 C613 C700 C701 C702 C703 C704 C705 C706 C710 C711 C712 C713 J1 J2 J3 J4 J5 J6 J7 J8 L600 L700 R1 R2 R3 R4 R5 R6 R7 R8 R9 R10 R11 R14 R16 R20 R21 R22 R23 R24 R25 R62 R66 R67 R601 R610 R613 R701 R710 R713 RTN6 SW6 SW-B TP1 TP2 U1 U600 U700
component class PMP20489_MainInput&MainChPowerStages: C11 C12 C13 C100 C101 C102 C103 C104 C105 C106 C110 C111 C112 C113 C200 C201 C202 C203 C204 C205 C206 C210 C211 C212 C213 C300 C301 C302 C303 C304 C305 C306 C310 C311 C312 C313 C400 C401 C402 C403 C404 C405 C406 C410 C411 C412 C413 C500 C501 C502 C503 C504 C505 C506 C510 C511 C512 C513 J11 J12 L100 L200 L300 L400 L500 R41 R42 R43 R101 R110 R113 R201 R210 R213 R301 R310 R313 R401 R410 R413 R501 R510 R513 RTN1 SW1 SW2 SW3 SW4 SW5 TP199 U100 U200 U300 U400 U500 VIN Vin_rtn
component class Header: J1 J2 J3 J4 J5 J7 J8 J540 J790 J800 J803
component class PMP20489_outputs_dynLoad_Bias_HDWR: C21 C22 C23 C24 C25 C26 C27 C28 C29 C30 C31 C32 C33 C34 C35 C36 C37 C38 C39 C40 C77 C540 C721 C722 C723 C724 C725 C726 C727 C728 C729 C730 C777 C790 C800 C801 C802 C803 C804 C900 C901 C902 C903 D500 D502 D503 D770 D771 D772 D800 Dyn_Clk FID1 FID2 FID3 FID4 FID5 FID6 H1 H2 H3 H4 J14 J15 J16 J17 J18 J77 J540 J541 J701 J702 J703 J777 J790 J791 J800 J803 L900 LBL1 Logo3 Q500 Q520 Q540 Q770 Q790 R71 R72 R77 R505 R506 R507 R508 R509 R511 R512 R514 R515 R516 R521 R522 R523 R525 R526 R527 R528 R529 R530 R531 R532 R533 R534 R535 R536 R540 R541 R542 R543 R550 R551 R552 R553 R770 R771 R772 R773 R774 R775 R776 R777 R778 R780 R781 R782 R783 R784 R785 R786 R787 R788 R790 R791 R792 R793 R800 R811 R812 U800 U801 U900 U901 Vout Vout_rtn VoutB VoutB_rtn ZZ2 ZZ3 ZZ4
component class FiducialMark: FID1 FID2 FID3 FID4 FID5 FID6
component class AssemblyNote: ZZ2 ZZ3 ZZ4
component class Label: LBL1

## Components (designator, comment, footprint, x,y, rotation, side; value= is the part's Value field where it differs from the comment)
C1 "GRM155R61A475M" 0402 440,2350 r180 top
C2 "C1608X5R1E105K080AC" 0603 445,2590 r180 top
C3 "C1005X7S1A105K050BC" 0402 460,2535 r180 top
C4 "C1005X7R1H222K" 0402 440,2450 r180 top
C5 "C1005X7R1H102K" 0402L 750,2260 r180 top
C6 "C1005X7S1A105K050BC" 0402 840,2550 r0 top
C7 "C1608X5R1E105K080AC" 0603 325,2220 r180 top
C8 "C1608X5R1E105K080AC" 0603 350,2620 r90 top
C11 "35ZL470MEFC10X20" ZL_1000x2000 240,4660 r180 top
C12 "35ZL470MEFC10X20" ZL_1000x2000 240,5100 r180 top
C13 "35ZL470MEFC10X20" ZL_1000x2000 240,5540 r180 top
C21 "EEFSX0E471ER" SP-Cap_Standard 2810,3970 r180 top
C22 "EEFSX0E471ER" SP-Cap_Standard 2810,4160 r180 top
C23 "EEFSX0E471ER" SP-Cap_Standard 2810,4360 r180 top
C24 "EEFSX0E471ER" SP-Cap_Standard 2810,4560 r180 top
C25 "EEFSX0E471ER" SP-Cap_Standard 2810,4760 r180 top
C26 "EEFSX0E471ER" SP-Cap_Standard 2810,3970 r180 bottom
C27 "EEFSX0E471ER" SP-Cap_Standard 2810,4160 r180 bottom
C28 "EEFSX0E471ER" SP-Cap_Standard 2810,4360 r180 bottom
C29 "EEFSX0E471ER" SP-Cap_Standard 2810,4560 r180 bottom
C30 "EEFSX0E471ER" SP-Cap_Standard 2810,4760 r180 bottom
C31 "C1210C107M9PACTU" 1210_280 2580,3480 r270 top
C32 "C1210C107M9PACTU" 1210_280 2710,3480 r270 top
C33 "C1210C107M9PACTU" 1210_280 2840,3480 r270 top
C34 "C1210C107M9PACTU" 1210_280 2970,3480 r270 top
C35 "C1210C107M9PACTU" 1210_280 3100,3480 r270 top
C36 "C1210C107M9PACTU" 1210_280 2580,3480 r270 bottom
C37 "C1210C107M9PACTU" 1210_280 2710,3480 r270 bottom
C38 "C1210C107M9PACTU" 1210_280 2840,3480 r270 bottom
C39 "C1210C107M9PACTU" 1210_280 2970,3480 r270 bottom
C40 "C1210C107M9PACTU" 1210_280 3100,3480 r270 bottom
C60 "C1005X7R1H102K" 0402 795,2645 r90 top
C77 "GRM155R61E104KA87D" 0402 3205,3480 r270 top
C100 "C1005C0G1E102J" 0402 1565,2245 r180 top
C101 "C3225X5R1C226M" 1210 1425,2500 r180 bottom
C102 "C3225X5R1C226M" 1210 1425,2500 r180 top
C103 "C3225X5R1C226M" 1210 1545,2650 r0 top
C104 "C3225X5R1C226M" 1210 1545,2780 r0 bottom
C105 "C3225X5R1C226M" 1210 1545,2780 r0 top
C106 "C1005X7R1H332K" 0402 1580,2560 r0 top
C110 "GRM155R61E104KA87D" 0402 1440,2395 r180 top
C111 "C0603C106M9PACTU" 0603L 1752,2360 r180 bottom
C112 "GRM155R61C104KA88D" 0402 1695,2245 r180 top
C113 "08051C152KAT2A" 0805_HV 1825,2600 r90 top
C200 "C1005C0G1E102J" 0402 1565,2905 r180 top
C201 "C3225X5R1C226M" 1210 1545,3300 r0 top
C202 "C3225X5R1C226M" 1210 1545,3300 r0 bottom
C203 "C3225X5R1C226M" 1210 1545,3430 r0 top
C204 "C3225X5R1C226M" 1210 1425,3150 r180 top
C205 "C3225X5R1C226M" 1210 1425,3150 r180 bottom
C206 "C1005X7R1H332K" 0402 1575,3215 r0 top
C210 "GRM155R61E104KA87D" 0402 1445,3060 r180 top
C211 "C0603C106M9PACTU" 0603L 1752,3020 r180 bottom
C212 "GRM155R61C104KA88D" 0402 1705,2905 r180 top
C213 "08051C152KAT2A" 0805_HV 1825,3260 r90 top
C300 "C1005C0G1E102J" 0402 1565,3595 r180 top
C301 "C3225X5R1C226M" 1210 1425.32,3850 r180 top
C302 "C3225X5R1C226M" 1210 1425.32,3850 r180 bottom
C303 "C3225X5R1C226M" 1210 1545,4010 r0 top
C304 "C3225X5R1C226M" 1210 1545,4010 r0 bottom
C305 "C3225X5R1C226M" 1210 1545,4140 r0 top
C306 "C1005X7R1H332K" 0402 1570,3910 r0 top
C310 "GRM155R61E104KA87D" 0402 1440,3750 r180 top
C311 "C0603C106M9PACTU" 0603L 1752,3711 r180 bottom
C312 "GRM155R61C104KA88D" 0402 1705,3595 r180 top
C313 "08051C152KAT2A" 0805_HV 1825,3930 r90 top
C400 "C1005C0G1E102J" 0402 1565,4265 r180 top
C401 "C3225X5R1C226M" 1210 1545,4670 r0 top
C402 "C3225X5R1C226M" 1210 1545,4670 r0 bottom
C403 "C3225X5R1C226M" 1210 1545,4800 r0 top
C404 "C3225X5R1C226M" 1210 1425,4510 r180 top
C405 "C3225X5R1C226M" 1210 1425,4510 r180 bottom
C406 "C1005X7R1H332K" 0402 1575,4580 r0 top
C410 "GRM155R61E104KA87D" 0402 1445,4420 r180 top
C411 "C0603C106M9PACTU" 0603L 1754,4380 r180 bottom
C412 "GRM155R61C104KA88D" 0402 1705,4265 r180 top
C413 "08051C152KAT2A" 0805_HV 1825,4620 r90 top
C500 "C1005C0G1E102J" 0402 1565,4925 r180 top
C501 "C3225X5R1C226M" 1210 1550,5320 r0 top
C502 "C3225X5R1C226M" 1210 1550,5320 r0 bottom
C503 "C3225X5R1C226M" 1210 1550,5450 r0 top
C504 "C3225X5R1C226M" 1210 1425,5180 r180 top
C505 "C3225X5R1C226M" 1210 1425,5180 r180 bottom
C506 "C1005X7R1H332K" 0402 1575,5235 r0 top
C510 "GRM155R61E104KA87D" 0402 1445,5080 r180 top
C511 "C0603C106M9PACTU" 0603L 1754,5040 r180 bottom
C512 "GRM155R61C104KA88D" 0402 1705,4925 r180 top
C513 "08051C152KAT2A" 0805_HV 1825,5280 r90 top
C540 "GRM155R61E104KA87D" 0402 3355,3405 r270 bottom
C600 "C1005C0G1E102J" 0402 1565,1235 r180 top
C601 "C3225X5R1C226M" 1210 1545,1765 r0 top
C602 "C3225X5R1C226M" 1210 1425,1495 r180 bottom
C603 "C3225X5R1C226M" 1210 1425,1495 r180 top
C604 "C3225X5R1C226M" 1210 1545,1635 r0 bottom
C605 "C3225X5R1C226M" 1210 1545,1635 r0 top
C606 "C1005X7R1H332K" 0402 1575,1545 r0 top
C610 "GRM155R61E104KA87D" 0402 1445,1390 r180 top
C611 "C0603C106M9PACTU" 0603L 1752,1350 r180 bottom
C612 "GRM155R61C104KA88D" 0402 1705,1235 r180 top
C613 "08051C152KAT2A" 0805_HV 1825,1590 r90 top
C700 "C1005C0G1E102J" 0402 1565,560 r180 top
C701 "C3225X5R1C226M" 1210 1545,960 r0 top
C702 "C3225X5R1C226M" 1210 1545,960 r0 bottom
C703 "C3225X5R1C226M" 1210 1425,825 r180 top
C704 "C3225X5R1C226M" 1210 1425,825 r180 bottom
C705 "C3225X5R1C226M" 1210 1545,1090 r0 top
C706 "C1005X7R1H332K" 0402 1575,870 r0 top
C710 "GRM155R61E104KA87D" 0402 1445,715 r180 top
C711 "C0603C106M9PACTU" 0603L 1752,675 r180 bottom
C712 "GRM155R61C104KA88D" 0402 1705,560 r180 top
C713 "08051C152KAT2A" 0805_HV 1825,915 r90 top
C721 "EEFSX0E471ER" SP-Cap_Standard 2870,1250 r180 top
C722 "EEFSX0E471ER" SP-Cap_Standard 2870,1440 r180 top
C723 "EEFSX0E471ER" SP-Cap_Standard 2870,1250 r180 bottom
C724 "EEFSX0E471ER" SP-Cap_Standard 2870,1440 r180 bottom
C725 "C1210C107M9PACTU" 1210_280 2840,1010 r270 top
C726 "C1210C107M9PACTU" 1210_280 2970,1010 r270 top
C727 "C1210C107M9PACTU" 1210_280 3100,1010 r270 top
C728 "C1210C107M9PACTU" 1210_280 2970,1010 r270 bottom
C729 "C1210C107M9PACTU" 1210_280 3100,1010 r270 bottom
C730 "C1210C107M9PACTU" 1210_280 2840,1010 r270 bottom
C777 "GRM155R61E104KA87D" 0402 3190,1000 r270 top
C790 "GRM155R61E104KA87D" 0402 3365,985 r270 bottom
C800 "C1005X7R1H104M" 0402 720,5610 r270 top
C801 "C1005X7R1H104M" 0402 990,5865 r0 top
C802 "C1005X7R1H104M" 0402 990,5815 r0 top
C803 "C1005X7R1H104M" 0402 1000,5660 r270 top
C804 "GRM155R61A105KE15D" 0402 1540,5650 r180 top
C900 "GRM31CR61E106KA12L" 1206_180 1020,870 r0 top
C901 "GRM31CR60J226KE19L" 1206_180 830,690 r90 top
C902 "C1608X5R1E105K080AC" 0603 465,585 r180 top
C903 "C1608X5R1E105K080AC" 0603 455.31,835 r180 top
D500 "LTST-C170KRKT" LED_LTST-C170_Red 2065,5745 r180 top
D502 "MBR0530T1G" SOD-123 2200,5555 r90 top
D503 "MBR0530T1G" SOD-123 2105,5555 r270 top
D770 "MBR0530T1G" SOD-123 2060,50 r180 top
D771 "MBR0530T1G" SOD-123 2280,50 r180 top
D772 "LTST-C170KGKT" LTST-C170KGKT_Green 2480,50 r0 top
D800 "BAT54WS-7-F" SOD-323 840,5810 r180 top
Dyn_Clk "5000" Keystone5000 1799.77,5819.65 r90 top
FID1 "Fiducial" Fiducial10-30 500,5875 r0 top
FID2 "Fiducial" Fiducial10-30 500,250 r0 top
FID3 "Fiducial" Fiducial10-30 3525,250 r0 top
FID4 "Fiducial" Fiducial10-30 500,5875 r90 bottom
FID5 "Fiducial" Fiducial10-30 500,250 r90 bottom
FID6 "Fiducial" Fiducial10-30 3525,250 r90 bottom
H1 "SJ61A2" Bumpon_SJ61A2 200,5800 r180 bottom
H2 "SJ61A2" Bumpon_SJ61A2 3800,5800 r180 bottom
H3 "SJ61A2" Bumpon_SJ61A2 200,200 r180 bottom
H4 "SJ61A2" Bumpon_SJ61A2 3800,200 r180 bottom
J1 "PEC05DAAN" CONN_PEC05DAAN 600,2950 r180 top locked
J2 "PBC03SAAN" PBC03SAAN 145,2455 r270 top
J3 "PBC03SAAN" PBC03SAAN 700,2030 r180 top
J4 "PBC03SAAN" PBC03SAAN 150,1930 r270 top
J5 "PBC02SAAN" Sullins_PBC02SAAN 400,2035 r90 top
J6 "5103308-1" CONN_5103308-1 590,1410 r180 top locked
J7 "PEC05DAAN" CONN_PEC05DAAN 705,1790 r180 top
J8 "PBC02SAAN" Sullins_PBC02SAAN 900,2755 r270 top
J11 "CB35-36-CY" CB35-36-CY 360,4000 r0 top
J12 "CB35-36-CY" CB35-36-CY 360,3330 r0 top
J14 "ED555/2DS" TERM_BLK_ED555-2DS 3830,3470 r90 top
J15 "CB70-14-CY" CB70-14-CY 3545,4740 r180 top
J16 "CB70-14-CY" CB70-14-CY 3545,4040 r180 top
J17 "CB70-14-CY" CB70-14-CY 3545,3040 r180 top
J18 "CB70-14-CY" CB70-14-CY 3545,2310 r180 top
J77 "U.FL-R-SMT-1" CONN_UFL-R-SMT-1 3320,3450 r0 top
J540 "TSW-102-07-G-S" TSW-102-07-G-S 3130,3860 r180 top
J541 "U.FL-R-SMT-1" CONN_UFL-R-SMT-1 3240,3380 r270 bottom
J701 "CB35-36-CY" CB35-36-CY 3650,1520 r180 top
J702 "CB35-36-CY" CB35-36-CY 3650,650 r180 top
J703 "ED555/2DS" TERM_BLK_ED555-2DS 3830,1000 r90 top
J777 "U.FL-R-SMT-1" CONN_UFL-R-SMT-1 3300,980 r0 top
J790 "TSW-102-07-G-S" TSW-102-07-G-S 3280,1400 r180 top
J791 "U.FL-R-SMT-1" CONN_UFL-R-SMT-1 3240,920 r270 bottom
J800 "PBC02SAAN" Sullins_PBC02SAAN 870,5370 r270 top
J803 "TSW-103-07-G-S" TSW-103-07-G-S 2350,5840 r0 top
L100 "FP1308-R21-R" IND_FP1308 2155,2460 r0 top
L200 "FP1308-R21-R" IND_FP1308 2155,3120 r0 top
L300 "FP1308-R21-R" IND_FP1308 2155,3810 r0 top
L400 "FP1308-R21-R" IND_FP1308 2155,4480 r0 top
L500 "FP1308-R21-R" IND_FP1308 2155,5140 r0 top
L600 "FP1308-R21-R" IND_FP1308 2155,1450 r0 top
L700 "FP1308-R21-R" IND_FP1308 2155,775 r0 top
L900 "VLF302512MT-2R2M" VLF302512MT 955,625 r270 top
LBL1 "Size: 0.65\" x 0.20 \"" Label_650x200 1000,125 r0 top
Logo3 "FCC disclaimer" FCC_disclaimer 2350,3380 r0 top
Q500 "CSD16408Q5C" TRANS_NexFET_Q5C 2900,5430 r0 bottom
Q520 "CSD16408Q5C" TRANS_NexFET_Q5C 2680,2010 r0 bottom
Q540 "CSD16325Q5" TRANS_NexFET_Q5 3440,3630 r90 bottom
Q770 "CSD16408Q5C" TRANS_NexFET_Q5C 2990,210 r90 bottom
Q790 "CSD16325Q5" TRANS_NexFET_Q5 3440,1170 r90 bottom
R1 "CRCW04021R00JNED" 0402 150,2205 r90 top
R2 "CRCW04029M76FKED" 0402 970,2560 r0 top
R3 "CRCW0402121KFKED" 0402 340,2465 r90 top
R4 "CRCW0402412KFKED" 0402 525,2700 r90 top
R5 "CRCW0402154KFKED" 0402 470,2710 r270 top
R6 "CRCW04029M76FKED" 0402 900,2335 r0 top
R7 "CRCW04024K75FKED" 0402 440,2300 r180 top
R8 "CRCW04024K75FKED" 0402 430,2400 r180 top
R9 "CRCW04029M76FKED" 0402L 750,2225 r0 top
R10 "CRCW04021R00JNED" 0402 330,2165 r180 top
R11 "RC0402JR-070RL" 0402L 750,2191 r0 top
R14 "CRCW04024K75FKED" 0402 440,2220 r0 top
R16 "CRCW04021R00JNED" 0402 670,1190 r180 top
R20 "CRCW040210K0FKED" 0402 365,1630 r180 top
R21 "CRCW040210K0FKED" 0402 365,1190 r180 top
R22 "CRCW040210K0FKED" 0402 510,1190 r0 top
R23 "CRCW04024K75FKED" 0402 580,1650 r0 top
R24 "CRCW04024K75FKED" 0402 390,1840 r180 top
R25 "CRCW04024K75FKED" 0402 390,1740 r0 top
R41 "CRCW040210R0JNED" 0402 730,4340 r270 top
R42 "CRCW040210R0JNED" 0402 645,4340 r270 top
R43 "ERJ-M1WTF1M0U" 2512 690,4490 r180 top
R62 "CRCW04020000Z0ED" 0402 840,2620 r90 top
R66 "RC0402JR-070RL" 0402 945,2280 r180 top
R67 "RC0402JR-070RL" 0402 1050,2280 r0 top
R71 "CRCW040249R9FKED" 0402 3955,3730 r90 bottom
R72 "CRCW040249R9FKED" 0402 3955,3350 r270 bottom
R77 "CRCW040249R9FKED" 0402 3230,3560 r180 top
R101 "CRCW040210K0FKED" 0402L 1740,2315 r0 bottom
R110 "CRCW04022R20JNED" 0402 1440,2345 r0 top
R113 "CRM1206-JW-1R0ELF" 1206 1715,2630 r90 top
R201 "CRCW040210K0FKED" 0402L 1740,2975 r0 bottom
R210 "CRCW04022R20JNED" 0402 1445,3010 r0 top
R213 "CRM1206-JW-1R0ELF" 1206 1715,3290 r90 top
R301 "CRCW040210K0FKED" 0402L 1740,3665 r0 bottom
R310 "CRCW04022R20JNED" 0402 1440,3700 r0 top
R313 "CRM1206-JW-1R0ELF" 1206 1725,3980 r90 top
R401 "CRCW040210K0FKED" 0402L 1745,4335 r0 bottom
R410 "CRCW04022R20JNED" 0402 1445,4370 r0 top
R413 "CRM1206-JW-1R0ELF" 1206 1715,4650 r90 top
R501 "CRCW040210K0FKED" 0402L 1740,4995 r0 bottom
R505 "CSRN2512FKR300" 2512 3870,5770 r90 top
R506 "CSRN2512FKR300" 2512 3700,5210 r270 bottom
R507 "CSRN2512FKR300" 2512 3870,5210 r270 top
R508 "CSRN2512FKR300" 2512 3360,5210 r270 bottom
R509 "CSRN2512FKR300" 2512 3530,5210 r270 top
R510 "CRCW04022R20JNED" 0402 1445,5030 r0 top
R511 "CSRN2512FKR300" 2512 3180,5210 r270 bottom
R512 "CSRN2512FKR300" 2512 3130,5770 r90 top
R513 "CRM1206-JW-1R0ELF" 1206 1715,5310 r90 top
R514 "CSRN2512FKR300" 2512 2970,5770 r90 bottom
R515 "CSRN2512FKR300" 2512 3460,5770 r90 top
R516 "CRCW040210K0FKED" 0402 2720,5480 r90 bottom
R521 "CRCW060375R0FKEA" 0603 2331.3,2051.65 r90 bottom
R522 "CRCW0603249RFKEA" 0603 2411.3,2051.65 r90 bottom
R523 "CRCW0402330RJNED" 0402 2050,5815 r180 top
R525 "CSRN2512FKR300" 2512 2365,1980 r180 top
R526 "CSRN2512FKR300" 2512 2365,1855 r180 bottom
R527 "CSRN2512FKR300" 2512 2680,1960 r270 top
R528 "CSRN2512FKR300" 2512 2685,1795 r180 bottom
R529 "CSRN2512FKR300" 2512 3030,1850 r0 top
R530 "CSRN2512FKR300" 2512 3030,1850 r0 bottom
R531 "CSRN2512FKR300" 2512 3030,2050 r0 top
R532 "CSRN2512FKR300" 2512 3110,2310 r90 bottom
R533 "CSRN2512FKR300" 2512 2930,2310 r90 top
R534 "CSRN2512FKR300" 2512 2750,2310 r90 bottom
R535 "CSRN2512FKR300" 2512 2570,2310 r90 top
R536 "CRCW040210K0FKED" 0402 2490,2060 r90 bottom
R540 "CRCW04021K00FKED" 0402 3180,3740 r270 bottom
R541 "CRCW040210K0FKED" 0402 3080,3740 r270 bottom
R542 "ERJ-M1WSF10MU" 2512 3565,3390 r0 bottom
R543 "CRCW040249R9FKED" 0402 3330,3475 r180 bottom
R550 "CSRN2512FKR300" 2512 3300,5770 r90 bottom
R551 "CRCW060375R0FKEA" 0603 2580,5470 r90 bottom
R552 "CRCW0603249RFKEA" 0603 2650,5470 r90 bottom
R553 "CSRN2512FKR300" 2512 2800,5770 r90 top
R601 "CRCW040210K0FKED" 0402L 1740,1305 r0 bottom
R610 "CRCW04022R20JNED" 0402 1445,1340 r0 top
R613 "CRM1206-JW-1R0ELF" 1206 1715,1620 r90 top
R701 "CRCW040210K0FKED" 0402L 1740,630 r0 bottom
R710 "CRCW04022R20JNED" 0402 1445,665 r0 top
R713 "CRM1206-JW-1R0ELF" 1206 1715,945 r90 top
R770 "CRCW0402330RJNED" 0402 2615,50 r180 bottom
R771 "CRCW040249R9FKED" 0402 3945,1270 r90 bottom
R772 "CRCW040249R9FKED" 0402 3945,900 r270 bottom
R773 "CRCW060375R0FKEA" 0603 2790,115 r0 bottom
R774 "CRCW0603249RFKEA" 0603 2790,50 r0 bottom
R775 "CSRN2512FKR300" 2512 1930,300 r90 bottom
R776 "CSRN2512FKR300" 2512 2120,300 r90 top
R777 "CSRN2512FKR300" 2512 2610,300 r90 bottom
R778 "CSRN2512FKR300" 2512 2300,300 r90 bottom
R780 "CSRN2512FKR300" 2512 3280,95 r0 bottom
R781 "CSRN2512FKR300" 2512 3290,535 r90 bottom
R782 "CSRN2512FKR300" 2512 2780,535 r90 top
R783 "CSRN2512FKR300" 2512 2950,535 r90 bottom
R784 "CSRN2512FKR300" 2512 3120,535 r90 top
R785 "CSRN2512FKR300" 2512 3280,280 r0 top
R786 "CSRN2512FKR300" 2512 2455,300 r90 top
R787 "CRCW040249R9FKED" 0402 3215,1090 r180 top
R788 "CRCW040210K0FKED" 0402 2940,40 r180 bottom
R790 "CRCW04021K00FKED" 0402 3305,1280 r270 bottom
R791 "CRCW040210K0FKED" 0402 3230,1280 r270 bottom
R792 "ERJ-M1WSF10MU" 2512 3560,930 r0 bottom
R793 "CRCW040249R9FKED" 0402 3265,1060 r180 bottom
R800 "CRCW04028K06FKED" 0402 720,5785 r270 top
R811 "CRCW040210K0FKED" 0402 1000,5545 r270 top
R812 "CRCW0402200KFKED" 0402 850,5870 r180 top
RTN1 "5016" Testpoint_Keystone_Compact 1120,3230 r0 top
RTN6 "5016" Testpoint_Keystone_Compact 1600,400 r0 top
SW1 "5015" Testpoint_Keystone_Miniature 1960,2780 r0 top
SW2 "5015" Testpoint_Keystone_Miniature 1950,3440 r0 top
SW3 "5015" Testpoint_Keystone_Miniature 1960,4130 r0 top
SW4 "5015" Testpoint_Keystone_Miniature 1960,4800 r0 top
SW5 "5015" Testpoint_Keystone_Miniature 1965,5460 r0 top
SW6 "5015" Testpoint_Keystone_Miniature 1960,1775 r0 top
SW-B "5015" Testpoint_Keystone_Miniature 1960,1100 r180 top
TP1 "5000" Keystone5000 110,2730 r0 top
TP2 "5000" Keystone5000 150,1680 r0 top
TP199 "5016" Testpoint_Keystone_Compact 1125,3565 r0 top
U1 "TPS53679RSB" RSB0040E 680,2410 r270 top
U100 "CSD95490Q5MC" DMC0012A 1635,2400 r180 top
U200 "CSD95490Q5MC" DMC0012A 1635,3060 r180 top
U300 "CSD95490Q5MC" DMC0012A 1635,3750 r180 top
U400 "CSD95490Q5MC" DMC0012A 1635,4420 r180 top
U500 "CSD95490Q5MC" DMC0012A 1635,5080 r180 top
U600 "CSD95490Q5MC" DMC0012A 1635,1390 r180 top
U700 "CSD95490Q5MC" DMC0012A 1635,715 r180 top
U800 "TLC555CD" D0008A_N 860,5610 r90 top
U801 "UCC27324D" D0008A_N 1540,5790 r0 top
U900 "TPS62163DSGR" DSG0008A 945,765 r270 top
U901 "TPS73233DBV" DBV0005A_N 475,715 r90 top
VIN "5000" Keystone5000 230,4340 r0 top
Vin_rtn "5001" Keystone5001 190,2945 r90 top
Vout "5000" Keystone5000 2610,3750 r0 top
Vout_rtn "5001" Keystone5001 2600,3280 r90 top
VoutB "5000" Keystone5000 2610,1150 r0 top
VoutB_rtn "5001" Keystone5001 2680,920 r90 top
ZZ2 "These assemblies are ESD sensitive, ESD precautions shall be observed." AssemblyNote 203,6498 r0 top
ZZ3 "These assemblies must be clean and free from flux and all contaminants. Use of no clean flux is not acceptable." AssemblyNote 203,6405 r0 top
ZZ4 "These assemblies must comply with workmanship standards IPC-A-610 Class 2, unless otherwise specified." AssemblyNote 203,6316 r0 top

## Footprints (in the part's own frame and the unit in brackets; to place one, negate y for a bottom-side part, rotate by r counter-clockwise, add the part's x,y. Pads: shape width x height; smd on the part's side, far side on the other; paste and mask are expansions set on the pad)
0402 [mm] "0402 from SM-752 data"
  rect 0.8x0.6 smd: 1(-0.6,0) 2(0.6,0)
  silkscreen extent -1.22,-0.52 1.22,0.52, body extent -0.55,-0.3 0.55,0.3, height 0.6
0402L [mm] "0402 from SM-752 data"
  rect 0.6x0.5 smd: 1(-0.5,0) 2(0.5,0)
  body extent -0.55,-0.3 0.55,0.3, height 0.6
0603 [mm] "0603 from SM-752 data"
  rect 1x0.95 smd: 1(-0.8,0) 2(0.8,0)
  silkscreen extent -1.52,-0.69 1.52,0.69, body extent -0.87,-0.47 0.87,0.47, height 1
0603L [mm] "0603 from SM-752 data"
  rect 0.8x0.85 smd: 1(-0.7,0) 2(0.7,0)
  silkscreen extent -0.07,-0.33 0.07,0.33, body extent -0.87,-0.47 0.87,0.47, height 1
0805_HV [mil] "0805 with 30mil clearance between pads"
  rect 50x63 smd: 1(-40,0) 2(40,0)
  silkscreen extent -74,-40 74,40, body extent -43,-29 43,29, height 57
1206 [mm] "1206 from SM-752 data"
  rect 1.3x1.85 smd: 1(-1.45,0) 2(1.45,0)
  silkscreen extent -2.4,-1.21 2.4,1.21, body extent -1.7,-0.9 1.7,0.9, height 1.35
1206_180 [mm] "1206_180"
  rect 1.1x1.6 smd: 1(-1.7,0) 2(1.7,0)
  silkscreen extent -0.9,-1 0.9,1, body extent -1.75,-0.95 1.75,0.95, height 1.8
1210 [mm] "1210 from SM-752 data"
  rect 1.3x2.7 smd: 1(-1.45,0) 2(1.45,0)
  silkscreen extent -2.32,-1.57 2.32,1.57, body extent -1.7,-1.35 1.7,1.35, height 1.35
1210_280 [mm] "SMD, 2-Leads, Body 3.6x2.8mm, Height 2.8mm"
  rect 1.1x2.2 smd: 1(-1.65,0) 2(1.65,0)
  silkscreen extent -0.84,-1.4 0.84,1.4, body extent -1.8,-1.4 1.8,1.4, height 2.8
2512 [mm] "Chip Resistor, Body 6.3x3.2mm, IPC Medium Density"
  rect 1.3x3.4 smd: 1(-2.95,0) 2(2.95,0)
  silkscreen extent -1.9,-1.6 1.9,1.6, body extent -3.22,-1.67 3.22,1.67, height 0.71
AssemblyNote [mil] "Assembly Note"
Bumpon_SJ61A2 [mil] "3M Hemispherical Bumpon transparent"
  round 1 on Mech4: 0(0,0)
  silkscreen extent -192,-192 192,192, body extent -193,-192 193,192, height 250
CB35-36-CY [mil] "Terminal 50A Lug"
  rect 550x380 hole 188 copper offset -45,0 paste-190: 1(0,0)
  body extent -960,-189 230,191, height 614
CB70-14-CY [mil] "Terminal 90A Lug"
  rect 680x500 hole 254 copper offset -90,0 paste-250: 1(0,0)
  body extent -1300,-260 250,260, height 714
CONN_5103308-1 [mm] "TE Connectivity (AMP) Rev E datasheet"
  rect 1.65x1.65 hole 1.016 mask+0: 1(-5.08,-1.27)
  round 1.65 hole 1.016 mask+0: 2(-5.08,1.27) 3(-2.54,-1.27) 4(-2.54,1.27) 5(0,-1.27) 6(0,1.27) 7(2.54,-1.27) 8(2.54,1.27) 9(5.08,-1.27) 10(5.08,1.27)
  silkscreen extent -10.16,-5.33 10.16,4.57, body extent -10.16,-4.57 10.16,4.57, height 9.87
CONN_PEC05DAAN [mm] "SULLINS"
  rect 1.65x1.65 hole 1.016 mask+0: 1(-5.08,-1.27)
  round 1.65 hole 1.016 mask+0: 2(-5.08,1.27) 3(-2.54,-1.27) 4(-2.54,1.27) 5(0,-1.27) 6(0,1.27) 7(2.54,-1.27) 8(2.54,1.27) 9(5.08,-1.27) 10(5.08,1.27)
  silkscreen extent -7.45,-2.6 6.35,2.54, body extent -6.35,-2.54 6.35,2.54, height 8.38
CONN_UFL-R-SMT-1 [mm] "Hirose recommended land pattern http://www.hirose.co.jp/cataloge_hp/e32119372.pdf 2009.2"
  rect 1.05x1 smd: 1(-1.525,0)
  rect 2.2x1.05 smd: 2(0,1.475) 3(0,-1.475)
  Top Layer keep-out region: -0.8,-0.7 1.1,-0.7 1.1,0.7 -0.8,0.7
  silkscreen extent -1.7,-1.7 1.7,1.7, body extent -1.55,-1.5 1.55,1.5, height 1.27
D0008A_N [mm] "SOIC, 8-Leads, Body 4.9x3.9mm, Pitch 1.27mm, IPC Medium Density"
  oval 1.45x0.6 smd: 1(-2.725,1.905) 2(-2.725,0.635) 3(-2.725,-0.635) 4(-2.725,-1.905) 5(2.725,-1.905) 6(2.725,-0.635) 7(2.725,0.635) 8(2.725,1.905)
  silkscreen extent -3.3,-2.5 0.9,2.5, body extent -3,-2.45 3,2.45, height 1.63
DBV0005A_N [mm] "SOT23, 5-Leads, Body 2.9x1.6mm, Pitch 0.95mm, Lead Span 2.8mm, IPC Medium Density"
  rrect17% 1x0.6 smd: 1(-1.375,0.95) 2(-1.375,0) 3(-1.375,-0.95) 4(1.375,-0.95) 5(1.375,0.95)
  silkscreen extent -1.63,-1.55 0.38,1.55, body extent -1.42,-1.46 1.42,1.46, height 1.09
DMC0012A [mm] "VSON-CLIP"
  rrect40% 0.7x0.25 smd: 1(-2.35,2.501) 2(-2.35,2.001) 3(-2.35,1.5) 4(-2.35,1) 5(-2.35,0.5) 8(2.35,0.5) 9(2.35,1) 10(2.35,1.5) 11(2.35,2.001) 12(2.35,2.501)
  rrect25% 0.8x2.85 smd paste-0.4 mask-0.4: 6(-2.35,-1.25) 7(2.35,-1.25)
  rrect9% 1.41x1.12 on Top Paste: 13(-0.805,1.98) 13(-0.805,0.66) 13(-0.805,-0.66) 13(-0.805,-1.98) 13(0.805,1.98) 13(0.805,0.66) 13(0.805,-0.66) 13(0.805,-1.98)
  rrect3% 3.3x5.4 smd paste-1.7: 13(0,0)
  silkscreen extent -2.7,-3.2 2.7,3.2, body extent -2.5,-3 2.5,3, height 1.05
DSG0008A [mm] "SON, 8-Leads, Body 2x2mm, Pitch 0.5mm, Thermal Pad 1.6x0.9mm, TI Recommended"
  rrect40% 0.5x0.25 smd: 1(-0.95,0.75) 2(-0.95,0.25) 3(-0.95,-0.25) 4(-0.95,-0.75) 5(0.95,-0.75) 6(0.95,-0.25) 7(0.95,0.25) 8(0.95,0.75)
  rrect11% 0.9x1.6 smd paste-0.45: 9(0,0)
  silkscreen extent -1.07,-1.15 1.07,1.15, body extent -1.05,-1.05 1.05,1.05, height 0.8
FCC_disclaimer [mil]
Fiducial10-30 [mm]
  round 1 smd mask+1: 1(0,0)
  Top Layer keep-out circle w1.678: c0,0 r0.75
IND_FP1308 [mm] "Coiltronics recommended land pattern 0911"
  rect 3.18x7.62 smd: 1(-5.19,0) 2(5.19,0)
  silkscreen extent -6.86,-6.6 6.86,6.6, body extent -6.85,-6.47 6.85,6.47, height 8
Keystone5000 [mil] "For Keystone 500x miniature loop terminals"
  round 80 hole 40: 1(0,0)
  silkscreen extent -58,-58 58,58, body extent -49,-49 49,49, height 182
Keystone5001 [mil] "For Keystone 500x miniature loop terminals"
  round 80 hole 40: 1(0,0)
  silkscreen extent -58,-58 58,58, body extent -49,-49 49,49, height 182
Label_650x200 [mil] "Thermal Transfer Label"
  silkscreen extent -325,-100 325,100, body extent -325,-100 325,100, height 1
LED_LTST-C170_Red [mm] "LITE-ON"
  rect 1.2x1.2 smd: 1(-1.05,0) 2(1.05,0)
  silkscreen extent -1.6,-1 2.2,1, body extent -1.05,-0.67 1.05,0.67, height 1.1
LTST-C170KGKT_Green [mm] "LITE-ON"
  rect 1.2x1.2 smd: 1(-1.05,0) 2(1.05,0)
  silkscreen extent -1.6,-1 2.2,1, body extent -1.05,-0.67 1.05,0.67, height 1.1
PBC03SAAN [mm] "Sullins 100mil, 1x3, 230 mil above insulator"
  rect 1.65x1.65 hole 1.016: 1(-2.54,0)
  round 1.65 hole 1.016: 2(0,0) 3(2.54,0)
  silkscreen extent -3.81,-1.27 3.81,1.27, body extent -3.81,-1.27 3.81,1.27, height 8.38
RSB0040E [mm] "QFN, 40-Leads, Body 5x5mm, Pitch 0.4mm, Thermal Pad 3.15x3.15mm, TI Recommended"
  oval 0.6x0.2 smd: 1(-2.45,1.8) 2(-2.45,1.4) 3(-2.45,1) 4(-2.45,0.6) 5(-2.45,0.2) 6(-2.45,-0.2) 7(-2.45,-0.6) 8(-2.45,-1) 9(-2.45,-1.4) 10(-2.45,-1.8) 21(2.45,-1.8) 22(2.45,-1.4) 23(2.45,-1) 24(2.45,-0.6) 25(2.45,-0.2) 26(2.45,0.2) 27(2.45,0.6) 28(2.45,1) 29(2.45,1.4) 30(2.45,1.8)
  oval 0.2x0.6 smd: 11(-1.8,-2.45) 12(-1.4,-2.45) 13(-1,-2.45) 14(-0.6,-2.45) 15(-0.2,-2.45) 16(0.2,-2.45) 17(0.6,-2.45) 18(1,-2.45) 19(1.4,-2.45) 20(1.8,-2.45) 31(1.8,2.45) 32(1.4,2.45) 33(1,2.45) 34(0.6,2.45) 35(0.2,2.45) 36(-0.2,2.45) 37(-0.6,2.45) 38(-1,2.45) 39(-1.4,2.45) 40(-1.8,2.45)
  rect 3.15x3.15 smd paste-1.575: 41(0,0)
  silkscreen extent -2.72,-2.73 2.72,2.73, body extent -2.57,-2.57 2.58,2.58, height 0.81
SOD-123 [mm] "On Semi recommended land pattern"
  rect 0.915x1.22 smd: 1(-1.637,0) 2(1.637,0)
  silkscreen extent -2.74,-1.17 2.03,1.17, body extent -1.93,-0.9 1.93,0.9, height 1.35
SOD-323 [mm] "NXP recommended land pattern"
  rect 0.6x0.6 smd paste-0.05: 1(-1.1,0) 2(1.1,0)
  silkscreen extent -2.06,-0.86 1.53,0.86, body extent -1.3,-0.67 1.3,0.68, height 1.1
SP-Cap_Standard [mm] "Recommended land pattern for standard Panasonic SP-CAP capacitors"
  rect 2.4x2.8 smd: 1(-3.2,0) 2(3.2,0)
  silkscreen extent -4.25,-2.34 3.75,2.34, body extent -3.75,-2.25 3.75,2.25, height 2.11
Sullins_PBC02SAAN [mm] "Sullins 100mil, 1x2, 230 mil above insulator"
  rect 1.65x1.65 hole 1.016: 1(0,1.27)
  round 1.65 hole 1.016: 2(0,-1.27)
  silkscreen extent -1.37,-2.54 1.27,3.1, body extent -1.27,-2.54 1.27,2.54, height 8.38
TERM_BLK_ED555-2DS [mil]
  rrect4% 100x100 hole 50: 1(0,0)
  round 100 hole 50: 2(138,0)
  silkscreen extent -93,-161 215,113, body extent -69,-150 207,106, height 323
Testpoint_Keystone_Compact [mil] "Compact SMT test point"
  rect 185x135 smd: 1(0,0)
  silkscreen extent -110,-80 110,80, body extent -75,-56 75,56, height 91
Testpoint_Keystone_Miniature [mil] "Miniature SMT test point"
  rect 135x70 smd: 1(0,0)
  silkscreen extent -78,-46 78,45, body extent -52,-20 52,20, height 61
TRANS_NexFET_Q5 [mm] "TI recommended land pattern (nominal) M0139-01"
  rect 0.75x0.675 smd mask+0.051: 1(-2.776,1.917) 2(-2.776,0.639) 3(-2.776,-0.639) 4(-2.776,-1.917)
  rect 0.655x0.675 smd mask+0.051: 5(2.776,-1.917) 6(2.776,-0.639) 7(2.776,0.639) 8(2.776,1.917)
  rect 4.295x4.51 smd paste-2.2 mask+0.051: 9(0.301,0)
  silkscreen extent -3.4,-2.8 3.4,2.8, body extent -3.05,-2.55 3.05,2.55, height 1.06
TRANS_NexFET_Q5C [mm] "TI recommended land pattern (nominal) M0139-01"
  rect 0.75x0.675 smd mask+0.051: 1(-2.776,1.917) 2(-2.776,0.639) 3(-2.776,-0.639) 4(-2.776,-1.917)
  rect 0.655x0.675 smd mask+0.051: 5(2.776,-1.917) 6(2.776,-0.639) 7(2.776,0.639) 8(2.776,1.917)
  rect 4.295x4.51 smd paste-2.2 mask+0.051: 10(0.301,0)
  silkscreen extent -3.4,-2.8 3.4,2.8, body extent -3.05,-2.55 3.05,2.55, height 1.06
TSW-102-07-G-S [mm] "Samtec 100mil, 1x2, 230 mil above insulator"
  rrect6% 1.65x1.65 hole 1.016: 1(-1.27,0)
  round 1.65 hole 1.016: 2(1.27,0)
  silkscreen extent -2.54,-1.27 2.54,1.65, body extent -2.54,-1.27 2.54,1.27, height 8.38
TSW-103-07-G-S [mm] "Samtec 100mil, 1x3, 230 mil above insulator"
  rect 1.65x1.65 hole 1.016: 1(-2.54,0)
  round 1.65 hole 1.016: 2(0,0) 3(2.54,0)
  silkscreen extent -3.81,-1.27 3.81,1.65, body extent -3.81,-1.27 3.81,1.27, height 8.38
VLF302512MT [mm] "TDK"
  rect 0.9x1.45 smd: 1(-0.85,0) 2(0.85,0)
  silkscreen extent -1.45,-1.68 1.45,1.68, body extent -1.35,-1.6 1.35,1.6, height 1.2
ZL_1000x2000 [mm] "Capacitor, Electrolytic, Radial; Body 10 x 20 mm (Dia.xH typ); Pin Spacing 5 mm (typ)"
  rect 1.5x1.5 hole 0.9: 1(-2.5,0)
  round 1.5 hole 0.9: 2(2.5,0)
  silkscreen extent -5.3,-5.3 5.3,5.3, body extent -5.21,-5.24 5.24,5.24, height 22.01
